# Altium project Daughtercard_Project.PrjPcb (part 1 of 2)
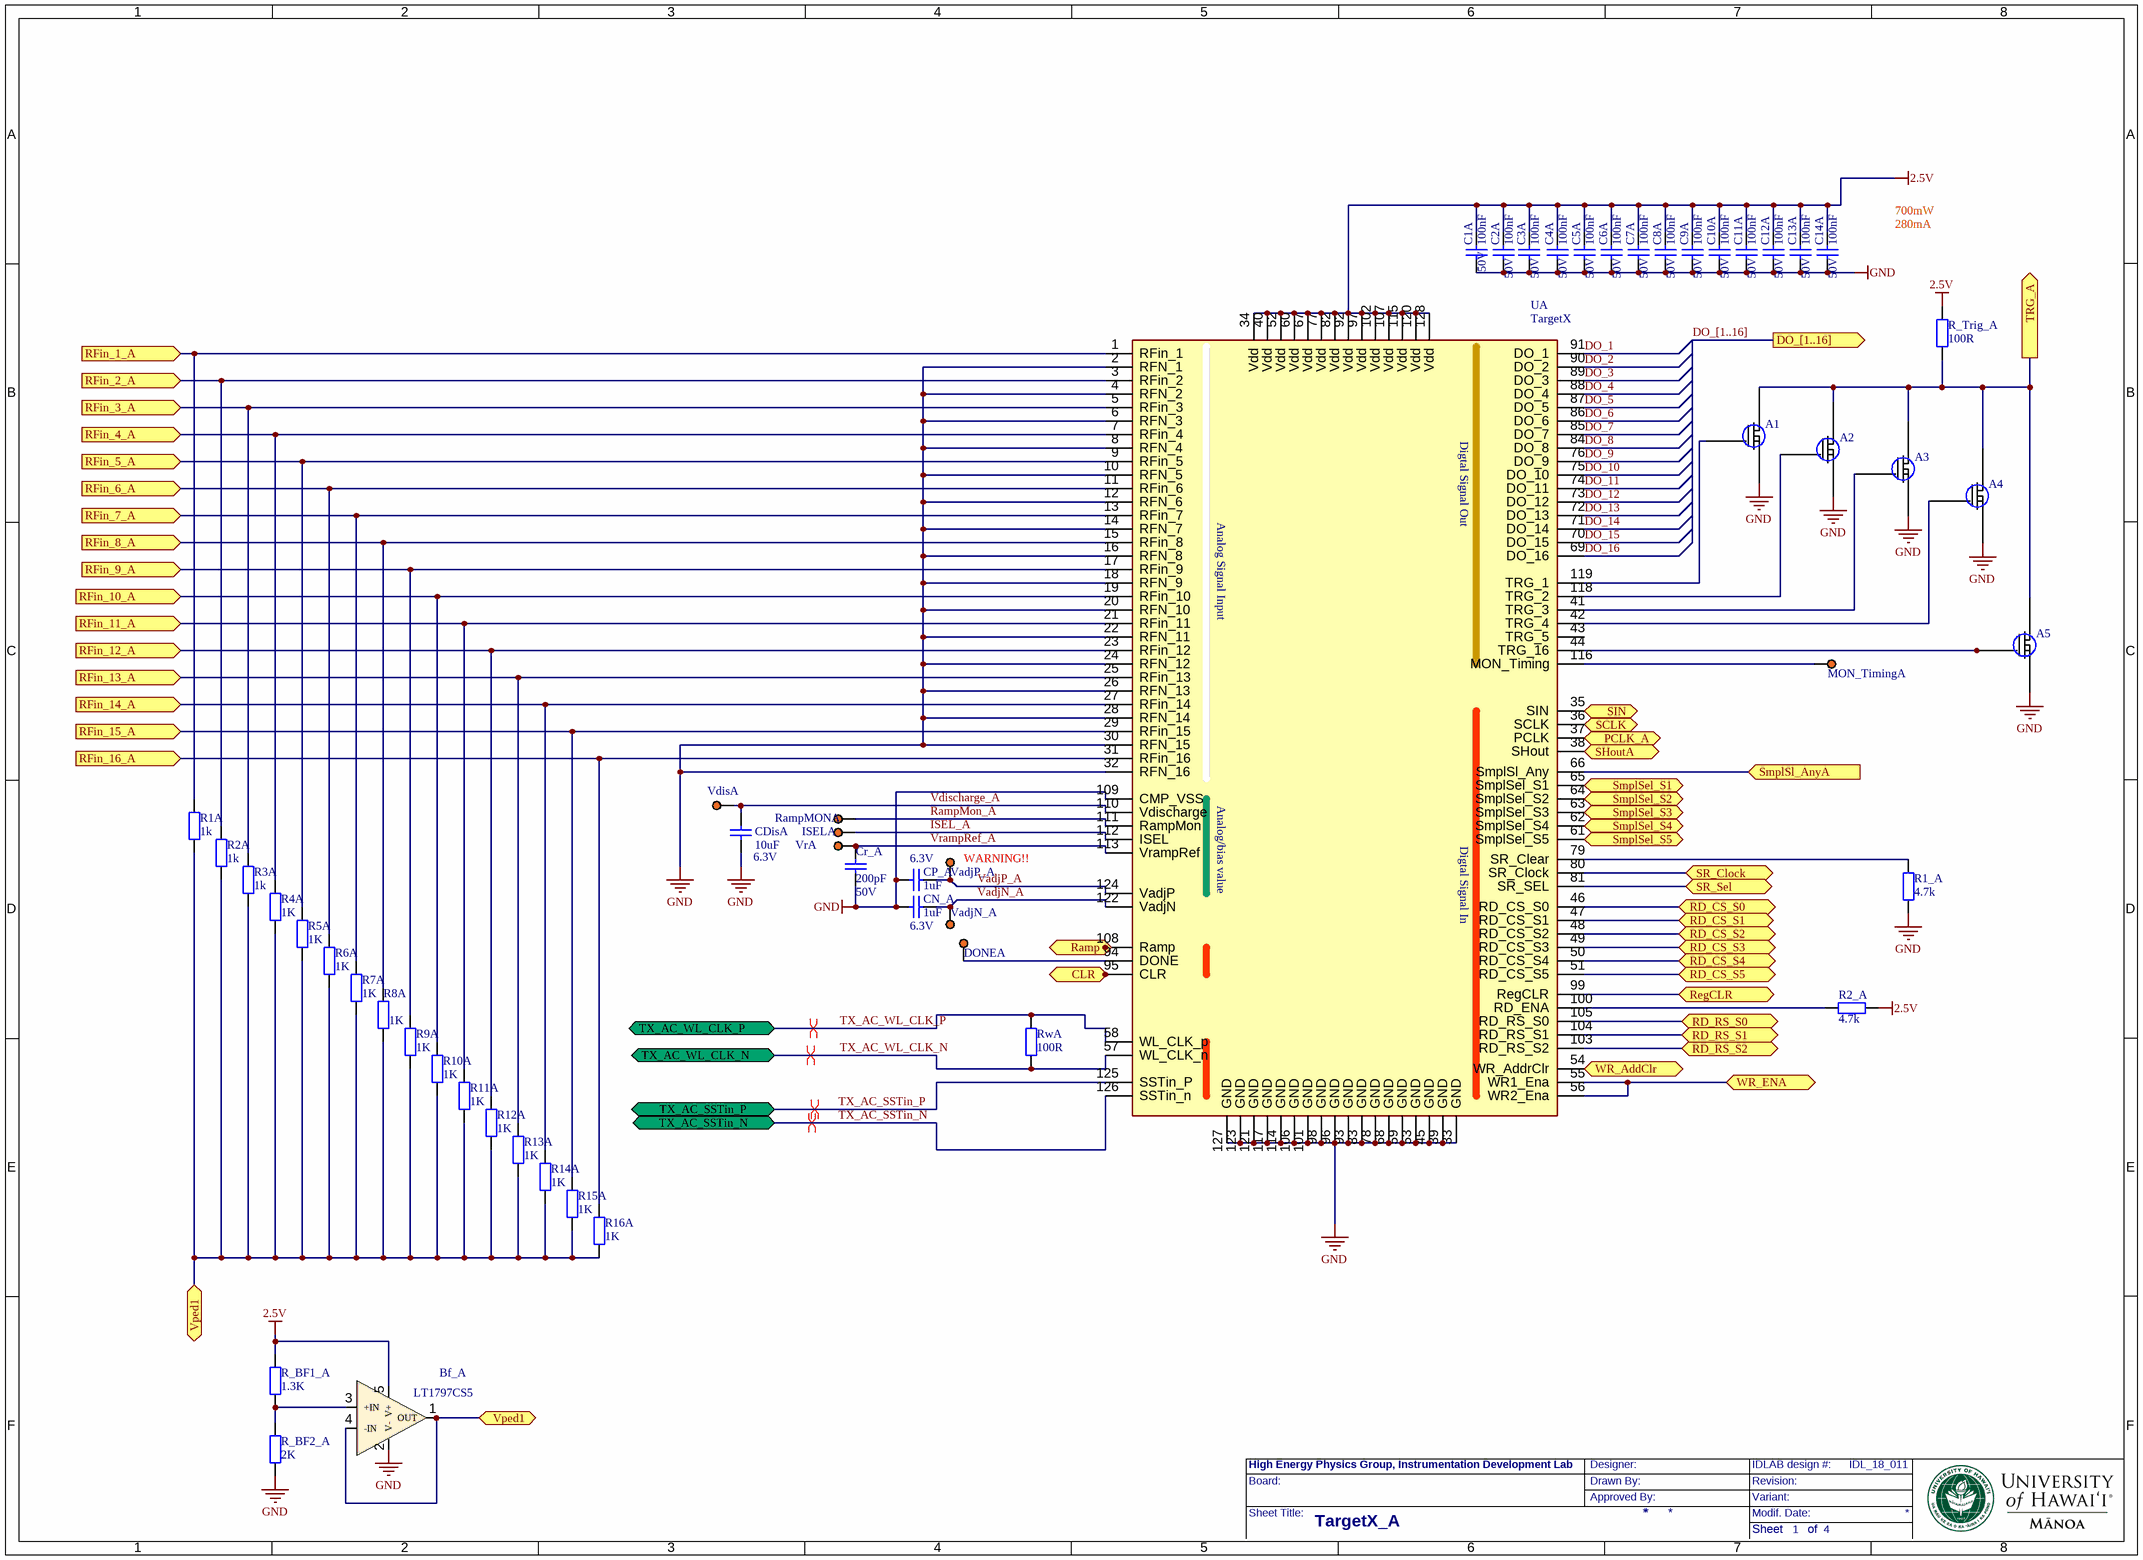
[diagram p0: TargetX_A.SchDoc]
5 sheets, 222 parts. Net scope: flat (ports and power ports of the same name join across sheets).
Board file: Daughter_Card_Tommy3.PcbDoc
Sheets:
  TargetX_A.SchDoc
  TargetX_B.SchDoc
  TargetX_C.SchDoc
  TargetX_D.SchDoc
  Daughtercard_Input_Output.SchDoc

## Sheet TargetX_A.SchDoc
size 401 x 291 mm; DocumentNumber: 1; SheetNumber: 1; SheetTotal: 4

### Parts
A1  MOSFET  [SOT-723]  (value not drawn)
A2  MOSFET  [SOT-723]  (value not drawn)
A3  MOSFET  [SOT-723]  (value not drawn)
A4  MOSFET  [SOT-723]  (value not drawn)
A5  MOSFET  [SOT-723]  (value not drawn)
Bf_A  LT1797CS5  [TSOT23-5]
C1A  100nF  Voltage rating: 50V  [CC0402N1R]
C2A  100nF  Voltage rating: 50V  [CC0402N1R]
C3A  100nF  Voltage rating: 50V  [CC0402N1R]
C4A  100nF  Voltage rating: 50V  [CC0402N1R]
C5A  100nF  Voltage rating: 50V  [CC0402N1R]
C6A  100nF  Voltage rating: 50V  [CC0402N1R]
C7A  100nF  Voltage rating: 50V  [CC0402N1R]
C8A  100nF  Voltage rating: 50V  [CC0402N1R]
C9A  100nF  Voltage rating: 50V  [CC0402N1R]
C10A  100nF  Voltage rating: 50V  [CC0402N1R]
C11A  100nF  Voltage rating: 50V  [CC0402N1R]
C12A  100nF  Voltage rating: 50V  [CC0402N1R]
C13A  100nF  Voltage rating: 50V  [CC0402N1R]
C14A  100nF  Voltage rating: 50V  [CC0402N1R]
CDisA  10uF  Voltage rating: 6.3V  [CC0402N1R]
CN_A  1uF  Voltage rating: 6.3V  [CC0402N1R]
CP_A  1uF  Voltage rating: 6.3V  [CC0402N1R]
Cr_A  200pF  Voltage rating: 50V  [CC0402N1R]
DONEA  SP1.5S  [SP1.5SQ]  (value not drawn)  (no BOM)
ISELA  SP1.5S  [SP1.5SQ]  (value not drawn)  (no BOM)
MON_TimingA  SP1.5S  [SP1.5SQ]  (value not drawn)  (no BOM)
R1_A  4.7k  [RC0603N1R]
R1A  1k  [RC0402N1R]
R2_A  4.7k  [RC0603N1R]
R2A  1k  [RC0402N1R]
R3A  1k  [RC0402N1R]
R4A  1K  [RC0402N1R]
R5A  1K  [RC0402N1R]
R6A  1K  [RC0402N1R]
R7A  1K  [RC0402N1R]
R8A  1K  [RC0402N1R]
R9A  1K  [RC0402N1R]
R10A  1K  [RC0402N1R]
R11A  1K  [RC0402N1R]
R12A  1K  [RC0402N1R]
R13A  1K  [RC0402N1R]
R14A  1K  [RC0402N1R]
R15A  1K  [RC0402N1R]
R16A  1K  [RC0402N1R]
R_BF1_A  1.3K  [RC0402N1R]
R_BF2_A  2K  [RC0402N1R]
R_Trig_A  100R  [RC0805N1R]
RampMONA  SP1.5S  [SP1.5SQ]  (value not drawn)  (no BOM)
RwA  100R  [RC0402N1R]
UA  TargetX  [TQFP128_MZA]
VadjN_A  SP1.5S  [SP1.5SQ]  (value not drawn)  (no BOM)
VadjP_A  SP1.5S  [SP1.5SQ]  (value not drawn)  (no BOM)
VdisA  SP1.5S  [SP1.5SQ]  (value not drawn)  (no BOM)
VrA  SP1.5S  [SP1.5SQ]  (value not drawn)  (no BOM)

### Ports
CLR (bidir), DO_[1..16] (out), PCLK_A (bidir), Ramp (bidir), RD_CS_S0 (bidir), RD_CS_S1 (bidir), RD_CS_S2 (bidir), RD_CS_S3 (bidir), RD_CS_S4 (bidir), RD_CS_S5 (bidir), RD_RS_S0 (bidir), RD_RS_S1 (bidir), RD_RS_S2 (bidir), RegCLR (bidir), RFin_1_A (in), RFin_2_A (in), RFin_3_A (in), RFin_4_A (in), RFin_5_A (in), RFin_6_A (in), RFin_7_A (in), RFin_8_A (in), RFin_9_A (in), RFin_10_A (in), RFin_11_A (in), RFin_12_A (in), RFin_13_A (in), RFin_14_A (in), RFin_15_A (in), RFin_16_A (in), SCLK (bidir), SHoutA (bidir), SIN (bidir), SmplSel_S1 (bidir), SmplSel_S2 (bidir), SmplSel_S3 (bidir), SmplSel_S4 (bidir), SmplSel_S5 (bidir), SmplSl_AnyA (in), SR_Clock (bidir), SR_Sel (bidir), TRG_A (out), TX_AC_SSTin_N (bidir), TX_AC_SSTin_P (bidir), TX_AC_WL_CLK_N (bidir), TX_AC_WL_CLK_P (bidir), Vped1 (bidir), WR_AddClr (bidir), WR_ENA (bidir)

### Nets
2.5V: Bf_A.5(V+) C1A.2 C2A.2 C3A.2 C4A.2 C5A.2 C6A.2 C7A.2 C8A.2 C9A.2 C10A.2 C11A.2 C12A.2 C13A.2 C14A.2 R2_A.1 R_BF1_A.2 R_Trig_A.2 UA.34(Vdd) UA.40(Vdd) UA.52(Vdd) UA.60(Vdd) UA.67(Vdd) UA.77(Vdd) UA.82(Vdd) UA.92(Vdd) UA.97(Vdd) UA.102(Vdd) UA.107(Vdd) UA.115(Vdd) UA.120(Vdd) UA.128(Vdd)
GND: A1.2(Source) A2.2(Source) A3.2(Source) A4.2(Source) A5.2(Source) Bf_A.2(V-) C1A.1 C2A.1 C3A.1 C4A.1 C5A.1 C6A.1 C7A.1 C8A.1 C9A.1 C10A.1 C11A.1 C12A.1 C13A.1 C14A.1 CDisA.1 CN_A.1 CP_A.1 Cr_A.1 R1_A.1 R_BF2_A.1 UA.2(RFN_1) UA.4(RFN_2) UA.6(RFN_3) UA.8(RFN_4) UA.10(RFN_5) UA.12(RFN_6) UA.14(RFN_7) UA.16(RFN_8) UA.18(RFN_9) UA.20(RFN_10) UA.22(RFN_11) UA.24(RFN_12) UA.26(RFN_13) UA.28(RFN_14) UA.30(RFN_15) UA.32(RFN_16) UA.33(GND) UA.39(GND) UA.45(GND) UA.53(GND) UA.59(GND) UA.68(GND) UA.78(GND) UA.83(GND) UA.93(GND) UA.96(GND) UA.98(GND) UA.101(GND) UA.106(GND) UA.109(CMP_VSS) UA.114(GND) UA.117(GND) UA.121(GND) UA.123(GND) UA.127(GND)
DO_1: UA.91(DO_1)
DO_2: UA.90(DO_2)
DO_3: UA.89(DO_3)
DO_4: UA.88(DO_4)
DO_5: UA.87(DO_5)
DO_6: UA.86(DO_6)
DO_7: UA.85(DO_7)
DO_8: UA.84(DO_8)
DO_9: UA.76(DO_9)
DO_10: UA.75(DO_10)
DO_11: UA.74(DO_11)
DO_12: UA.73(DO_12)
DO_13: UA.72(DO_13)
DO_14: UA.71(DO_14)
DO_15: UA.70(DO_15)
DO_16: UA.69(DO_16)
ISEL_A: ISELA.1 UA.112(ISEL)
PCLK_A: UA.37(PCLK) ; port PCLK_A
RampMon_A: RampMONA.1 UA.111(RampMon)
RD_CS_S0: UA.46(RD_CS_S0) ; port RD_CS_S0
RD_CS_S1: UA.47(RD_CS_S1) ; port RD_CS_S1
RD_CS_S2: UA.48(RD_CS_S2) ; port RD_CS_S2
RD_CS_S3: UA.49(RD_CS_S3) ; port RD_CS_S3
RD_CS_S4: UA.50(RD_CS_S4) ; port RD_CS_S4
RD_CS_S5: UA.51(RD_CS_S5) ; port RD_CS_S5
RD_RS_S0: UA.105(RD_RS_S0) ; port RD_RS_S0
RD_RS_S1: UA.104(RD_RS_S1) ; port RD_RS_S1
RD_RS_S2: UA.103(RD_RS_S2) ; port RD_RS_S2
RegCLR: UA.99(RegCLR) ; port RegCLR
RFin_1_A: R1A.2 UA.1(RFin_1) ; port RFin_1_A
RFin_2_A: R2A.2 UA.3(RFin_2) ; port RFin_2_A
RFin_3_A: R3A.2 UA.5(RFin_3) ; port RFin_3_A
RFin_4_A: R4A.2 UA.7(RFin_4) ; port RFin_4_A
RFin_5_A: R5A.2 UA.9(RFin_5) ; port RFin_5_A
RFin_6_A: R6A.2 UA.11(RFin_6) ; port RFin_6_A
RFin_7_A: R7A.2 UA.13(RFin_7) ; port RFin_7_A
RFin_8_A: R8A.2 UA.15(RFin_8) ; port RFin_8_A
RFin_9_A: R9A.2 UA.17(RFin_9) ; port RFin_9_A
RFin_10_A: R10A.2 UA.19(RFin_10) ; port RFin_10_A
RFin_11_A: R11A.2 UA.21(RFin_11) ; port RFin_11_A
RFin_12_A: R12A.2 UA.23(RFin_12) ; port RFin_12_A
RFin_13_A: R13A.2 UA.25(RFin_13) ; port RFin_13_A
RFin_14_A: R14A.2 UA.27(RFin_14) ; port RFin_14_A
RFin_15_A: R15A.2 UA.29(RFin_15) ; port RFin_15_A
RFin_16_A: R16A.2 UA.31(RFin_16) ; port RFin_16_A
SCLK: UA.36(SCLK) ; port SCLK
SHoutA: UA.38(SHout) ; port SHoutA
SIN: UA.35(SIN) ; port SIN
SmplSel_S1: UA.65(SmplSel_S1) ; port SmplSel_S1
SmplSel_S2: UA.64(SmplSel_S2) ; port SmplSel_S2
SmplSel_S3: UA.63(SmplSel_S3) ; port SmplSel_S3
SmplSel_S4: UA.62(SmplSel_S4) ; port SmplSel_S4
SmplSel_S5: UA.61(SmplSel_S5) ; port SmplSel_S5
SmplSl_AnyA: UA.66(SmplSl_Any) ; port SmplSl_AnyA
SR_Clock: UA.80(SR_Clock) ; port SR_Clock
SR_Sel: UA.81(SR_SEL) ; port SR_Sel
TRG_A: A1.3(Drain) A2.3(Drain) A3.3(Drain) A4.3(Drain) A5.3(Drain) R_Trig_A.1 ; port TRG_A
TX_AC_SSTin_N: UA.126(SSTin_n) ; port TX_AC_SSTin_N
TX_AC_SSTin_P: UA.125(SSTin_P) ; port TX_AC_SSTin_P
TX_AC_WL_CLK_N: RwA.1 UA.57(WL_CLK_n) ; port TX_AC_WL_CLK_N
TX_AC_WL_CLK_P: RwA.2 UA.58(WL_CLK_p) ; port TX_AC_WL_CLK_P
VadjN_A: CN_A.2 UA.122(VadjN) VadjN_A.1
VadjP_A: CP_A.2 UA.124(VadjP) VadjP_A.1
Vdischarge_A: CDisA.2 UA.110(Vdischarge) VdisA.1
Vped1: Bf_A.1(OUT) Bf_A.4(-IN) R1A.1 R2A.1 R3A.1 R4A.1 R5A.1 R6A.1 R7A.1 R8A.1 R9A.1 R10A.1 R11A.1 R12A.1 R13A.1 R14A.1 R15A.1 R16A.1 ; port Vped1
VrampRef_A: Cr_A.2 UA.113(VrampRef) VrA.1
WR_AddClr: UA.54(WR_AddrClr) ; port WR_AddClr
WR_ENA: UA.55(WR1_Ena) UA.56(WR2_Ena) ; port WR_ENA
NetA1_1: A1.1(Gate) UA.119(TRG_1)
NetA2_1: A2.1(Gate) UA.118(TRG_2)
NetA3_1: A3.1(Gate) UA.41(TRG_3)
NetA4_1: A4.1(Gate) UA.42(TRG_4)
NetA5_1: A5.1(Gate) UA.44(TRG_16)
NetBf_A_3: Bf_A.3(+IN) R_BF1_A.1 R_BF2_A.2
NetDONEA_1: DONEA.1 UA.94(DONE)
NetMON_TimingA_1: MON_TimingA.1 UA.116(MON_Timing)
NetR1_A_2: R1_A.2 UA.79(SR_Clear)
NetR2_A_2: R2_A.2 UA.100(RD_ENA)

Not connected (* = marked no-connect by the designer): UA 43(TRG_5) 95(CLR) 108(Ramp)

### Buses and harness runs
bus DO_[1..16] = port DO_[1..16]

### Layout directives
differential pair; rule Differential Pairs Routing [Pref Gap = 10mil    Min Gap  = 10mil    Max Gap  = 10milPref Width = 15mil    Min Width  = 15mil    Max Width  = 15mil]: TX_AC_SSTin_N, TX_AC_SSTin_P, TX_AC_WL_CLK_N, TX_AC_WL_CLK_P

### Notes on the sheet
- 700mW
- 280mA
- (near VadjP_A) WARNING!!
- Board:
- High Energy Physics Group, Instrumentation Development Lab
- Drawn By:
- Designer:
- Approved By:
- Revision:
- IDLAB design #:
- Variant:
- IDL_18_011
- Sheet Title:
- TargetX_A
- Modif. Date:
- Sheet       of

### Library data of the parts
A1-A5 = RUM001L02: N-Channel 20V 100mA (Ta) 150mW (Ta) Surface Mount VMT3
Bf_A = LT1797CS5#TRMPBF: Buffer Op-Amp
C1A C2A C3A C4A C5A C6A C7A C8A C9A C10A C11A C12A C13A C14A = CAPCC0402_100N_50VX7R: 0.10µF 50V Ceramic Capacitor X7R 0402; Manufacturer: TDK; Manufacturer No: C1005X7R1H104K050BB; Tech: SMDR
CDisA CN_A CP_A = CAPCC0402_1.0U_50VX7R: 1µF 6.3V Ceramic Capacitor X7R 0402; Manufacturer: TDK; Manufacturer No: GRM155R70J105KA12D; Tech: SMDR
Cr_A = CAPCC0402_200P_50VNP0: Capacitor chip ceramic 0402 50V NPO; Manufacturer: Murata; Manufacturer No: GRM1555C1H201JA01D; Tech: SMDR
DONEA ISELA MON_TimingA RampMONA VadjN_A VadjP_A VdisA VrA = SP1.5S: Wire solder pin 1.5mm; Sort: 610; Tech: THDW
R1_A R2_A = RES0603-1-1.00K-1%100PPM: Chip Resistor 0603 100mW 1% 100ppm; Manufacturer: Yageo; Manufacturer No: RC0603FR-071KL; Tech: SMDR
R1A R2A R3A R4A R5A R6A R7A R8A R9A R10A R11A R12A R13A R14A R15A R16A R_BF1_A R_BF2_A = RES0402-0-0R-1%100PPM: Chip Resistor 0402 62.5mW 1% 100ppm; Manufacturer: Panasonic; Manufacturer No: ERJ-2GE0R00X; Tech: SMDR
R_Trig_A = RES0805: Chip Resistor 0805; Tech: SMDR; Comment2: 0.125W 1% 200ppm; Sort: 110
RwA = RES0402-100R-1%100PPM: RES SMD 100 OHM 1% 1/10W 0402; Manufacturer: Panasonic; Manufacturer No: ERJ-2RKF1000X; Tech: SMDR
UA = DIGITZ_TargetX: 16-channel, 1GSPS Transient Waveform Recorder; Manufacturer: UHM_IDL; Tech: SMDR

## Sheet TargetX_B.SchDoc
size 401 x 291 mm; DocumentNumber: 2; SheetNumber: 2; SheetTotal: 4
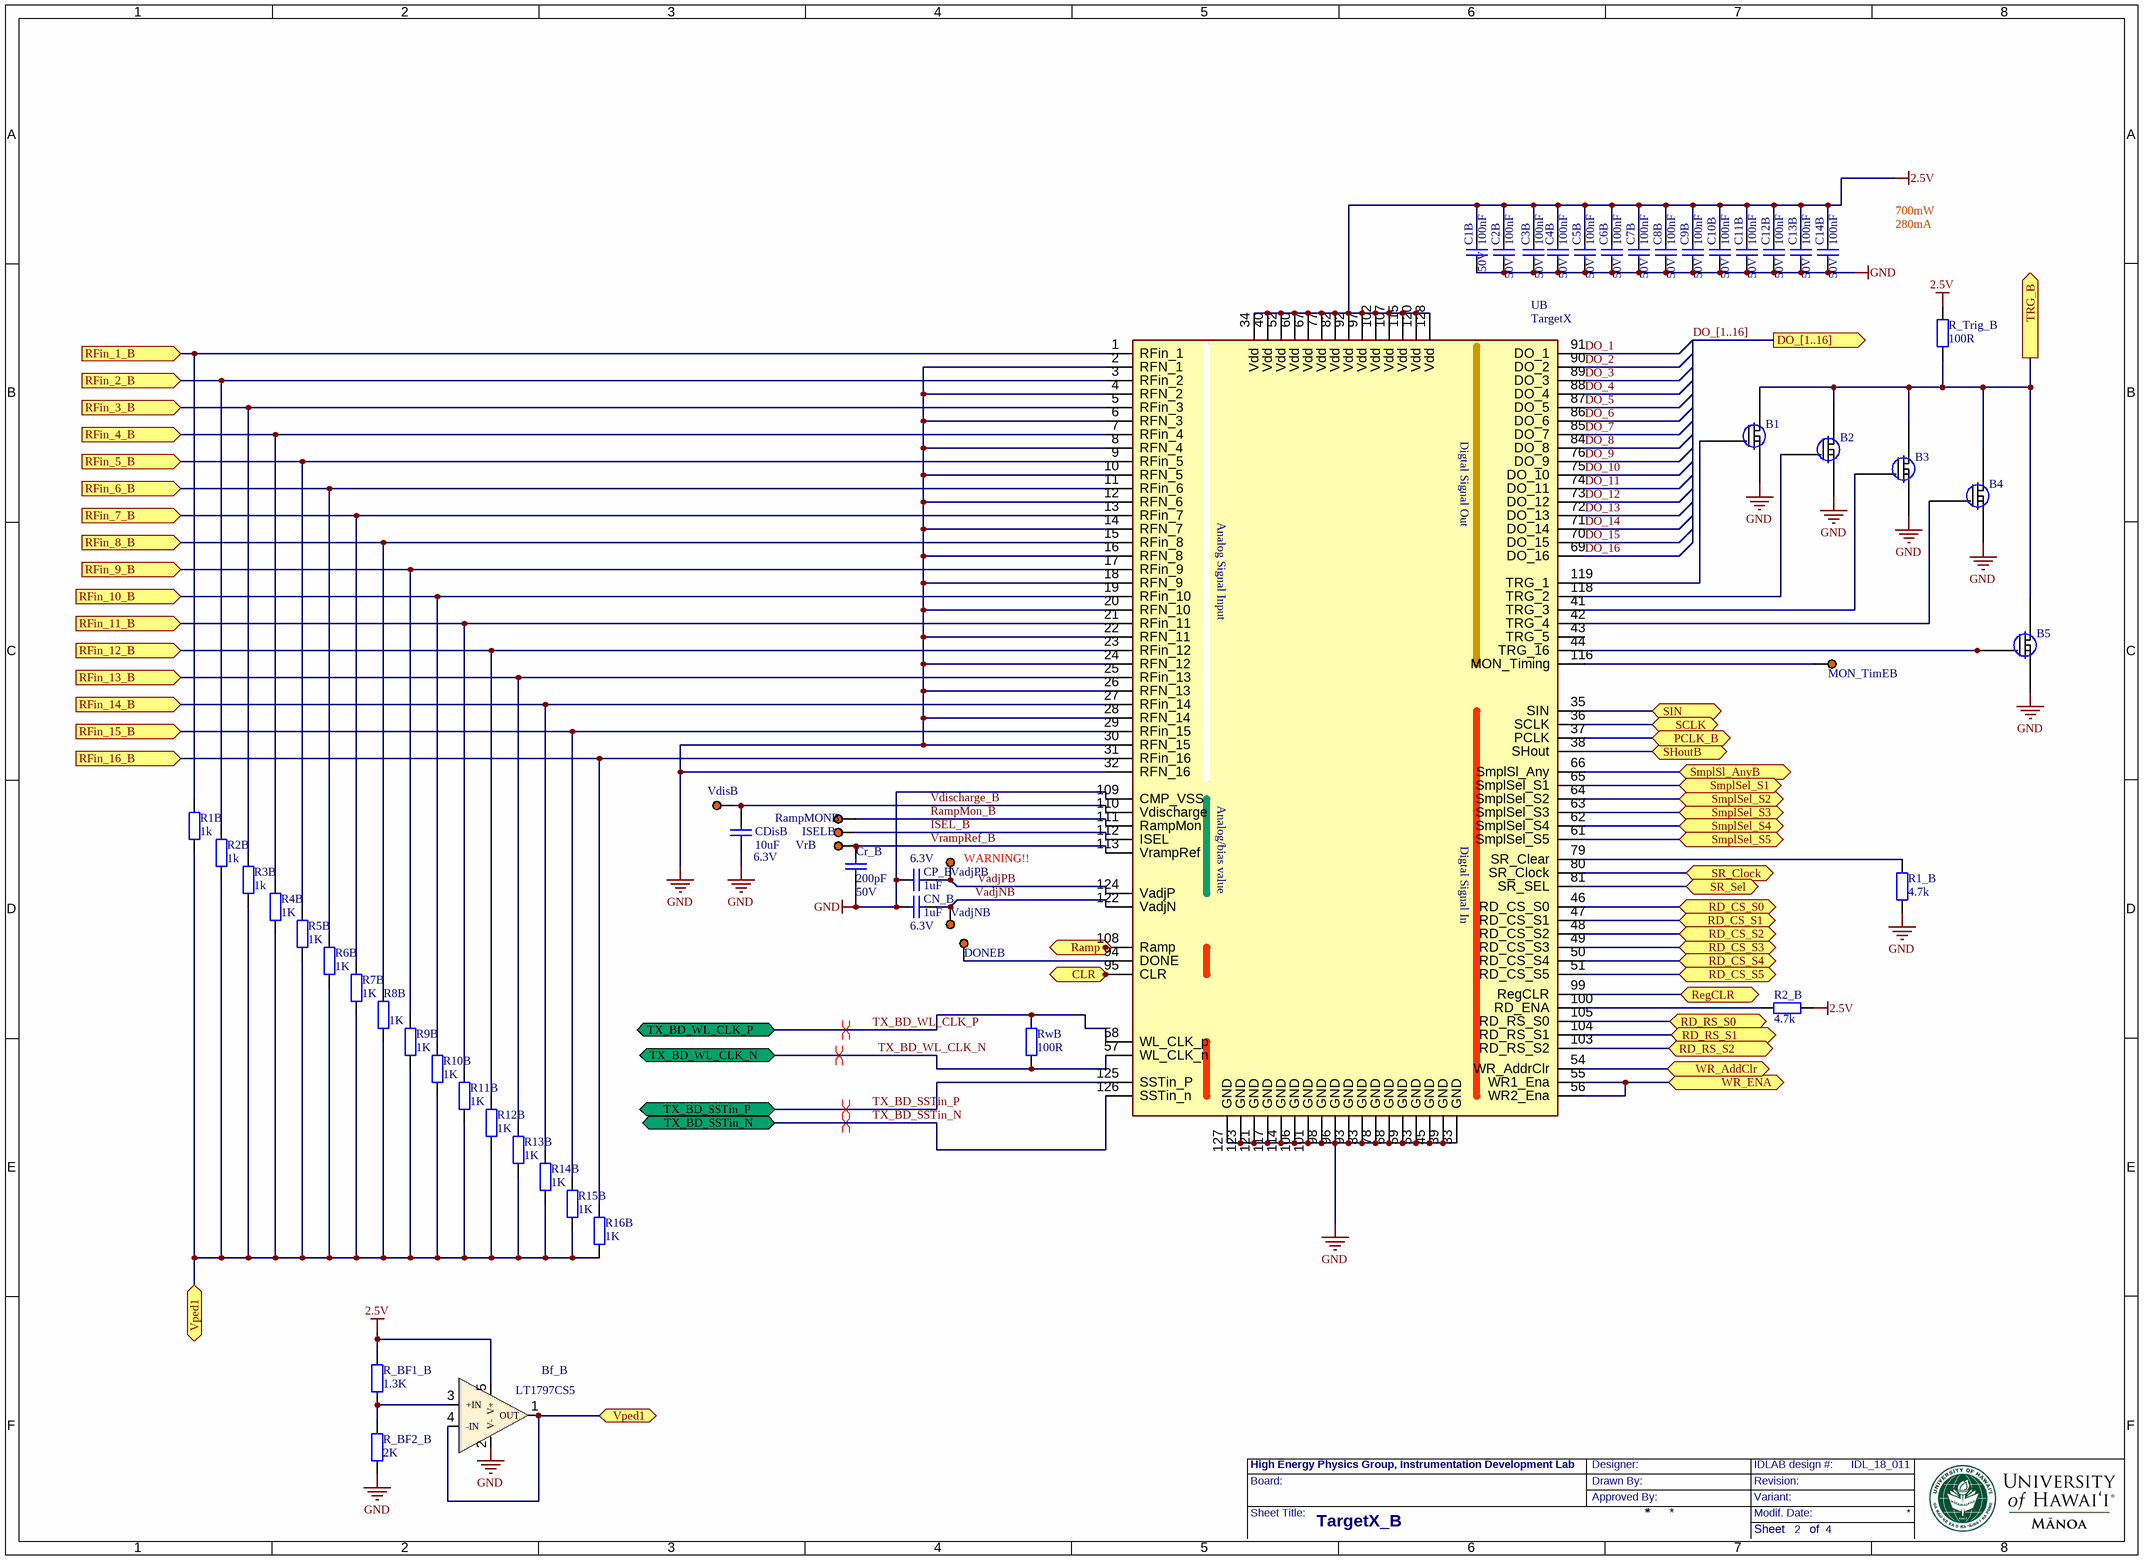
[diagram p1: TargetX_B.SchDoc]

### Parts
B1  MOSFET  [SOT-723]  (value not drawn)
B2  MOSFET  [SOT-723]  (value not drawn)
B3  MOSFET  [SOT-723]  (value not drawn)
B4  MOSFET  [SOT-723]  (value not drawn)
B5  MOSFET  [SOT-723]  (value not drawn)
Bf_B  LT1797CS5  [TSOT23-5]
C1B  100nF  Voltage rating: 50V  [CC0402N1R]
C2B  100nF  Voltage rating: 50V  [CC0402N1R]
C3B  100nF  Voltage rating: 50V  [CC0402N1R]
C4B  100nF  Voltage rating: 50V  [CC0402N1R]
C5B  100nF  Voltage rating: 50V  [CC0402N1R]
C6B  100nF  Voltage rating: 50V  [CC0402N1R]
C7B  100nF  Voltage rating: 50V  [CC0402N1R]
C8B  100nF  Voltage rating: 50V  [CC0402N1R]
C9B  100nF  Voltage rating: 50V  [CC0402N1R]
C10B  100nF  Voltage rating: 50V  [CC0402N1R]
C11B  100nF  Voltage rating: 50V  [CC0402N1R]
C12B  100nF  Voltage rating: 50V  [CC0402N1R]
C13B  100nF  Voltage rating: 50V  [CC0402N1R]
C14B  100nF  Voltage rating: 50V  [CC0402N1R]
CDisB  10uF  Voltage rating: 6.3V  [CC0402N1R]
CN_B  1uF  Voltage rating: 6.3V  [CC0402N1R]
CP_B  1uF  Voltage rating: 6.3V  [CC0402N1R]
Cr_B  200pF  Voltage rating: 50V  [CC0402N1R]
DONEB  SP1.5S  [SP1.5SQ]  (value not drawn)  (no BOM)
ISELB  SP1.5S  [SP1.5SQ]  (value not drawn)  (no BOM)
MON_TimEB  SP1.5S  [SP1.5SQ]  (value not drawn)  (no BOM)
R1_B  4.7k  [RC0603N1R]
R1B  1k  [RC0402N1R]
R2_B  4.7k  [RC0603N1R]
R2B  1k  [RC0402N1R]
R3B  1k  [RC0402N1R]
R4B  1K  [RC0402N1R]
R5B  1K  [RC0402N1R]
R6B  1K  [RC0402N1R]
R7B  1K  [RC0402N1R]
R8B  1K  [RC0402N1R]
R9B  1K  [RC0402N1R]
R10B  1K  [RC0402N1R]
R11B  1K  [RC0402N1R]
R12B  1K  [RC0402N1R]
R13B  1K  [RC0402N1R]
R14B  1K  [RC0402N1R]
R15B  1K  [RC0402N1R]
R16B  1K  [RC0402N1R]
R_BF1_B  1.3K  [RC0402N1R]
R_BF2_B  2K  [RC0402N1R]
R_Trig_B  100R  [RC0805N1R]
RampMONB  SP1.5S  [SP1.5SQ]  (value not drawn)  (no BOM)
RwB  100R  [RC0402N1R]
UB  TargetX  [TQFP128_MZA]
VadjNB  SP1.5S  [SP1.5SQ]  (value not drawn)  (no BOM)
VadjPB  SP1.5S  [SP1.5SQ]  (value not drawn)  (no BOM)
VdisB  SP1.5S  [SP1.5SQ]  (value not drawn)  (no BOM)
VrB  SP1.5S  [SP1.5SQ]  (value not drawn)  (no BOM)

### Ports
CLR (bidir), DO_[1..16] (out), PCLK_B (bidir), Ramp (bidir), RD_CS_S0 (bidir), RD_CS_S1 (bidir), RD_CS_S2 (bidir), RD_CS_S3 (bidir), RD_CS_S4 (bidir), RD_CS_S5 (bidir), RD_RS_S0 (bidir), RD_RS_S1 (bidir), RD_RS_S2 (bidir), RegCLR (bidir), RFin_1_B (in), RFin_2_B (in), RFin_3_B (in), RFin_4_B (in), RFin_5_B (in), RFin_6_B (in), RFin_7_B (in), RFin_8_B (in), RFin_9_B (in), RFin_10_B (in), RFin_11_B (in), RFin_12_B (in), RFin_13_B (in), RFin_14_B (in), RFin_15_B (in), RFin_16_B (in), SCLK (bidir), SHoutB (bidir), SIN (bidir), SmplSel_S1 (bidir), SmplSel_S2 (bidir), SmplSel_S3 (bidir), SmplSel_S4 (bidir), SmplSel_S5 (bidir), SmplSl_AnyB (bidir), SR_Clock (bidir), SR_Sel (bidir), TRG_B (out), TX_BD_SSTin_N (bidir), TX_BD_SSTin_P (bidir), TX_BD_WL_CLK_N (bidir), TX_BD_WL_CLK_P (bidir), Vped1 (bidir), WR_AddClr (bidir), WR_ENA (bidir)

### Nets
2.5V: Bf_B.5(V+) C1B.2 C2B.2 C3B.2 C4B.2 C5B.2 C6B.2 C7B.2 C8B.2 C9B.2 C10B.2 C11B.2 C12B.2 C13B.2 C14B.2 R2_B.1 R_BF1_B.2 R_Trig_B.2 UB.34(Vdd) UB.40(Vdd) UB.52(Vdd) UB.60(Vdd) UB.67(Vdd) UB.77(Vdd) UB.82(Vdd) UB.92(Vdd) UB.97(Vdd) UB.102(Vdd) UB.107(Vdd) UB.115(Vdd) UB.120(Vdd) UB.128(Vdd)
GND: B1.2 B2.2 B3.2 B4.2 B5.2 Bf_B.2(V-) C1B.1 C2B.1 C3B.1 C4B.1 C5B.1 C6B.1 C7B.1 C8B.1 C9B.1 C10B.1 C11B.1 C12B.1 C13B.1 C14B.1 CDisB.1 CN_B.1 CP_B.1 Cr_B.1 R1_B.1 R_BF2_B.1 UB.2(RFN_1) UB.4(RFN_2) UB.6(RFN_3) UB.8(RFN_4) UB.10(RFN_5) UB.12(RFN_6) UB.14(RFN_7) UB.16(RFN_8) UB.18(RFN_9) UB.20(RFN_10) UB.22(RFN_11) UB.24(RFN_12) UB.26(RFN_13) UB.28(RFN_14) UB.30(RFN_15) UB.32(RFN_16) UB.33(GND) UB.39(GND) UB.45(GND) UB.53(GND) UB.59(GND) UB.68(GND) UB.78(GND) UB.83(GND) UB.93(GND) UB.96(GND) UB.98(GND) UB.101(GND) UB.106(GND) UB.109(CMP_VSS) UB.114(GND) UB.117(GND) UB.121(GND) UB.123(GND) UB.127(GND)
DO_1: UB.91(DO_1)
DO_2: UB.90(DO_2)
DO_3: UB.89(DO_3)
DO_4: UB.88(DO_4)
DO_5: UB.87(DO_5)
DO_6: UB.86(DO_6)
DO_7: UB.85(DO_7)
DO_8: UB.84(DO_8)
DO_9: UB.76(DO_9)
DO_10: UB.75(DO_10)
DO_11: UB.74(DO_11)
DO_12: UB.73(DO_12)
DO_13: UB.72(DO_13)
DO_14: UB.71(DO_14)
DO_15: UB.70(DO_15)
DO_16: UB.69(DO_16)
ISEL_B: ISELB.1 UB.112(ISEL)
PCLK_B: UB.37(PCLK) ; port PCLK_B
RampMon_B: RampMONB.1 UB.111(RampMon)
RD_CS_S0: UB.46(RD_CS_S0) ; port RD_CS_S0
RD_CS_S1: UB.47(RD_CS_S1) ; port RD_CS_S1
RD_CS_S2: UB.48(RD_CS_S2) ; port RD_CS_S2
RD_CS_S3: UB.49(RD_CS_S3) ; port RD_CS_S3
RD_CS_S4: UB.50(RD_CS_S4) ; port RD_CS_S4
RD_CS_S5: UB.51(RD_CS_S5) ; port RD_CS_S5
RD_RS_S0: UB.105(RD_RS_S0) ; port RD_RS_S0
RD_RS_S1: UB.104(RD_RS_S1) ; port RD_RS_S1
RD_RS_S2: UB.103(RD_RS_S2) ; port RD_RS_S2
RegCLR: UB.99(RegCLR) ; port RegCLR
RFin_1_B: R1B.2 UB.1(RFin_1) ; port RFin_1_B
RFin_2_B: R2B.2 UB.3(RFin_2) ; port RFin_2_B
RFin_3_B: R3B.2 UB.5(RFin_3) ; port RFin_3_B
RFin_4_B: R4B.2 UB.7(RFin_4) ; port RFin_4_B
RFin_5_B: R5B.2 UB.9(RFin_5) ; port RFin_5_B
RFin_6_B: R6B.2 UB.11(RFin_6) ; port RFin_6_B
RFin_7_B: R7B.2 UB.13(RFin_7) ; port RFin_7_B
RFin_8_B: R8B.2 UB.15(RFin_8) ; port RFin_8_B
RFin_9_B: R9B.2 UB.17(RFin_9) ; port RFin_9_B
RFin_10_B: R10B.2 UB.19(RFin_10) ; port RFin_10_B
RFin_11_B: R11B.2 UB.21(RFin_11) ; port RFin_11_B
RFin_12_B: R12B.2 UB.23(RFin_12) ; port RFin_12_B
RFin_13_B: R13B.2 UB.25(RFin_13) ; port RFin_13_B
RFin_14_B: R14B.2 UB.27(RFin_14) ; port RFin_14_B
RFin_15_B: R15B.2 UB.29(RFin_15) ; port RFin_15_B
RFin_16_B: R16B.2 UB.31(RFin_16) ; port RFin_16_B
SCLK: UB.36(SCLK) ; port SCLK
SHoutB: UB.38(SHout) ; port SHoutB
SIN: UB.35(SIN) ; port SIN
SmplSel_S1: UB.65(SmplSel_S1) ; port SmplSel_S1
SmplSel_S2: UB.64(SmplSel_S2) ; port SmplSel_S2
SmplSel_S3: UB.63(SmplSel_S3) ; port SmplSel_S3
SmplSel_S4: UB.62(SmplSel_S4) ; port SmplSel_S4
SmplSel_S5: UB.61(SmplSel_S5) ; port SmplSel_S5
SmplSl_AnyB: UB.66(SmplSl_Any) ; port SmplSl_AnyB
SR_Clock: UB.80(SR_Clock) ; port SR_Clock
SR_Sel: UB.81(SR_SEL) ; port SR_Sel
TRG_B: B1.3 B2.3 B3.3 B4.3 B5.3 R_Trig_B.1 ; port TRG_B
TX_BD_SSTin_N: UB.126(SSTin_n) ; port TX_BD_SSTin_N
TX_BD_SSTin_P: UB.125(SSTin_P) ; port TX_BD_SSTin_P
TX_BD_WL_CLK_N: RwB.1 UB.57(WL_CLK_n) ; port TX_BD_WL_CLK_N
TX_BD_WL_CLK_P: RwB.2 UB.58(WL_CLK_p) ; port TX_BD_WL_CLK_P
VadjNB: CN_B.2 UB.122(VadjN) VadjNB.1
VadjPB: CP_B.2 UB.124(VadjP) VadjPB.1
Vdischarge_B: CDisB.2 UB.110(Vdischarge) VdisB.1
Vped1: Bf_B.1(OUT) Bf_B.4(-IN) R1B.1 R2B.1 R3B.1 R4B.1 R5B.1 R6B.1 R7B.1 R8B.1 R9B.1 R10B.1 R11B.1 R12B.1 R13B.1 R14B.1 R15B.1 R16B.1 ; port Vped1
VrampRef_B: Cr_B.2 UB.113(VrampRef) VrB.1
WR_AddClr: UB.54(WR_AddrClr) ; port WR_AddClr
WR_ENA: UB.55(WR1_Ena) UB.56(WR2_Ena) ; port WR_ENA
NetB1_1: B1.1 UB.119(TRG_1)
NetB2_1: B2.1 UB.118(TRG_2)
NetB3_1: B3.1 UB.41(TRG_3)
NetB4_1: B4.1 UB.42(TRG_4)
NetB5_1: B5.1 UB.44(TRG_16)
NetBf_B_3: Bf_B.3(+IN) R_BF1_B.1 R_BF2_B.2
NetDONEB_1: DONEB.1 UB.94(DONE)
NetMON_TimEB_1: MON_TimEB.1 UB.116(MON_Timing)
NetR1_B_2: R1_B.2 UB.79(SR_Clear)
NetR2_B_2: R2_B.2 UB.100(RD_ENA)

Not connected (* = marked no-connect by the designer): UB 43(TRG_5) 95(CLR) 108(Ramp)

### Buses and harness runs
bus DO_[1..16] = port DO_[1..16]

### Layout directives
differential pair: TX_BD_SSTin_N, TX_BD_SSTin_P, TX_BD_WL_CLK_N, TX_BD_WL_CLK_P

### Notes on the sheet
- 700mW
- 280mA
- (near VadjPB) WARNING!!
- Board:
- High Energy Physics Group, Instrumentation Development Lab
- Drawn By:
- Designer:
- Approved By:
- Revision:
- IDLAB design #:
- Variant:
- IDL_18_011
- Sheet Title:
- TargetX_B
- Modif. Date:
- Sheet       of

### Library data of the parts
B1-B5 = RUM001L02: as A1 on sheet TargetX_A
Bf_B = LT1797CS5#TRMPBF: Buffer Op-Amp
C1B C2B C3B C4B C5B C6B C7B C8B C9B C10B C11B C12B C13B C14B = CAPCC0402_100N_50VX7R: as C1A on sheet TargetX_A
CDisB CN_B CP_B = CAPCC0402_1.0U_50VX7R: as CDisA on sheet TargetX_A
Cr_B = CAPCC0402_200P_50VNP0: as Cr_A on sheet TargetX_A
DONEB ISELB MON_TimEB RampMONB VadjNB VadjPB VdisB VrB = SP1.5S: as DONEA on sheet TargetX_A
R1_B R2_B = RES0603-1-1.00K-1%100PPM: as R1_A on sheet TargetX_A
R1B R2B R3B R4B R5B R6B R7B R8B R9B R10B R11B R12B R13B R14B R15B R16B R_BF1_B R_BF2_B = RES0402-0-0R-1%100PPM: as R1A on sheet TargetX_A
R_Trig_B = RES0805: as R_Trig_A on sheet TargetX_A
RwB = RES0402-100R-1%100PPM: as RwA on sheet TargetX_A
UB = DIGITZ_TargetX: as UA on sheet TargetX_A

## Sheet TargetX_C.SchDoc
size 401 x 291 mm; DocumentNumber: 3; SheetNumber: 3; SheetTotal: 4
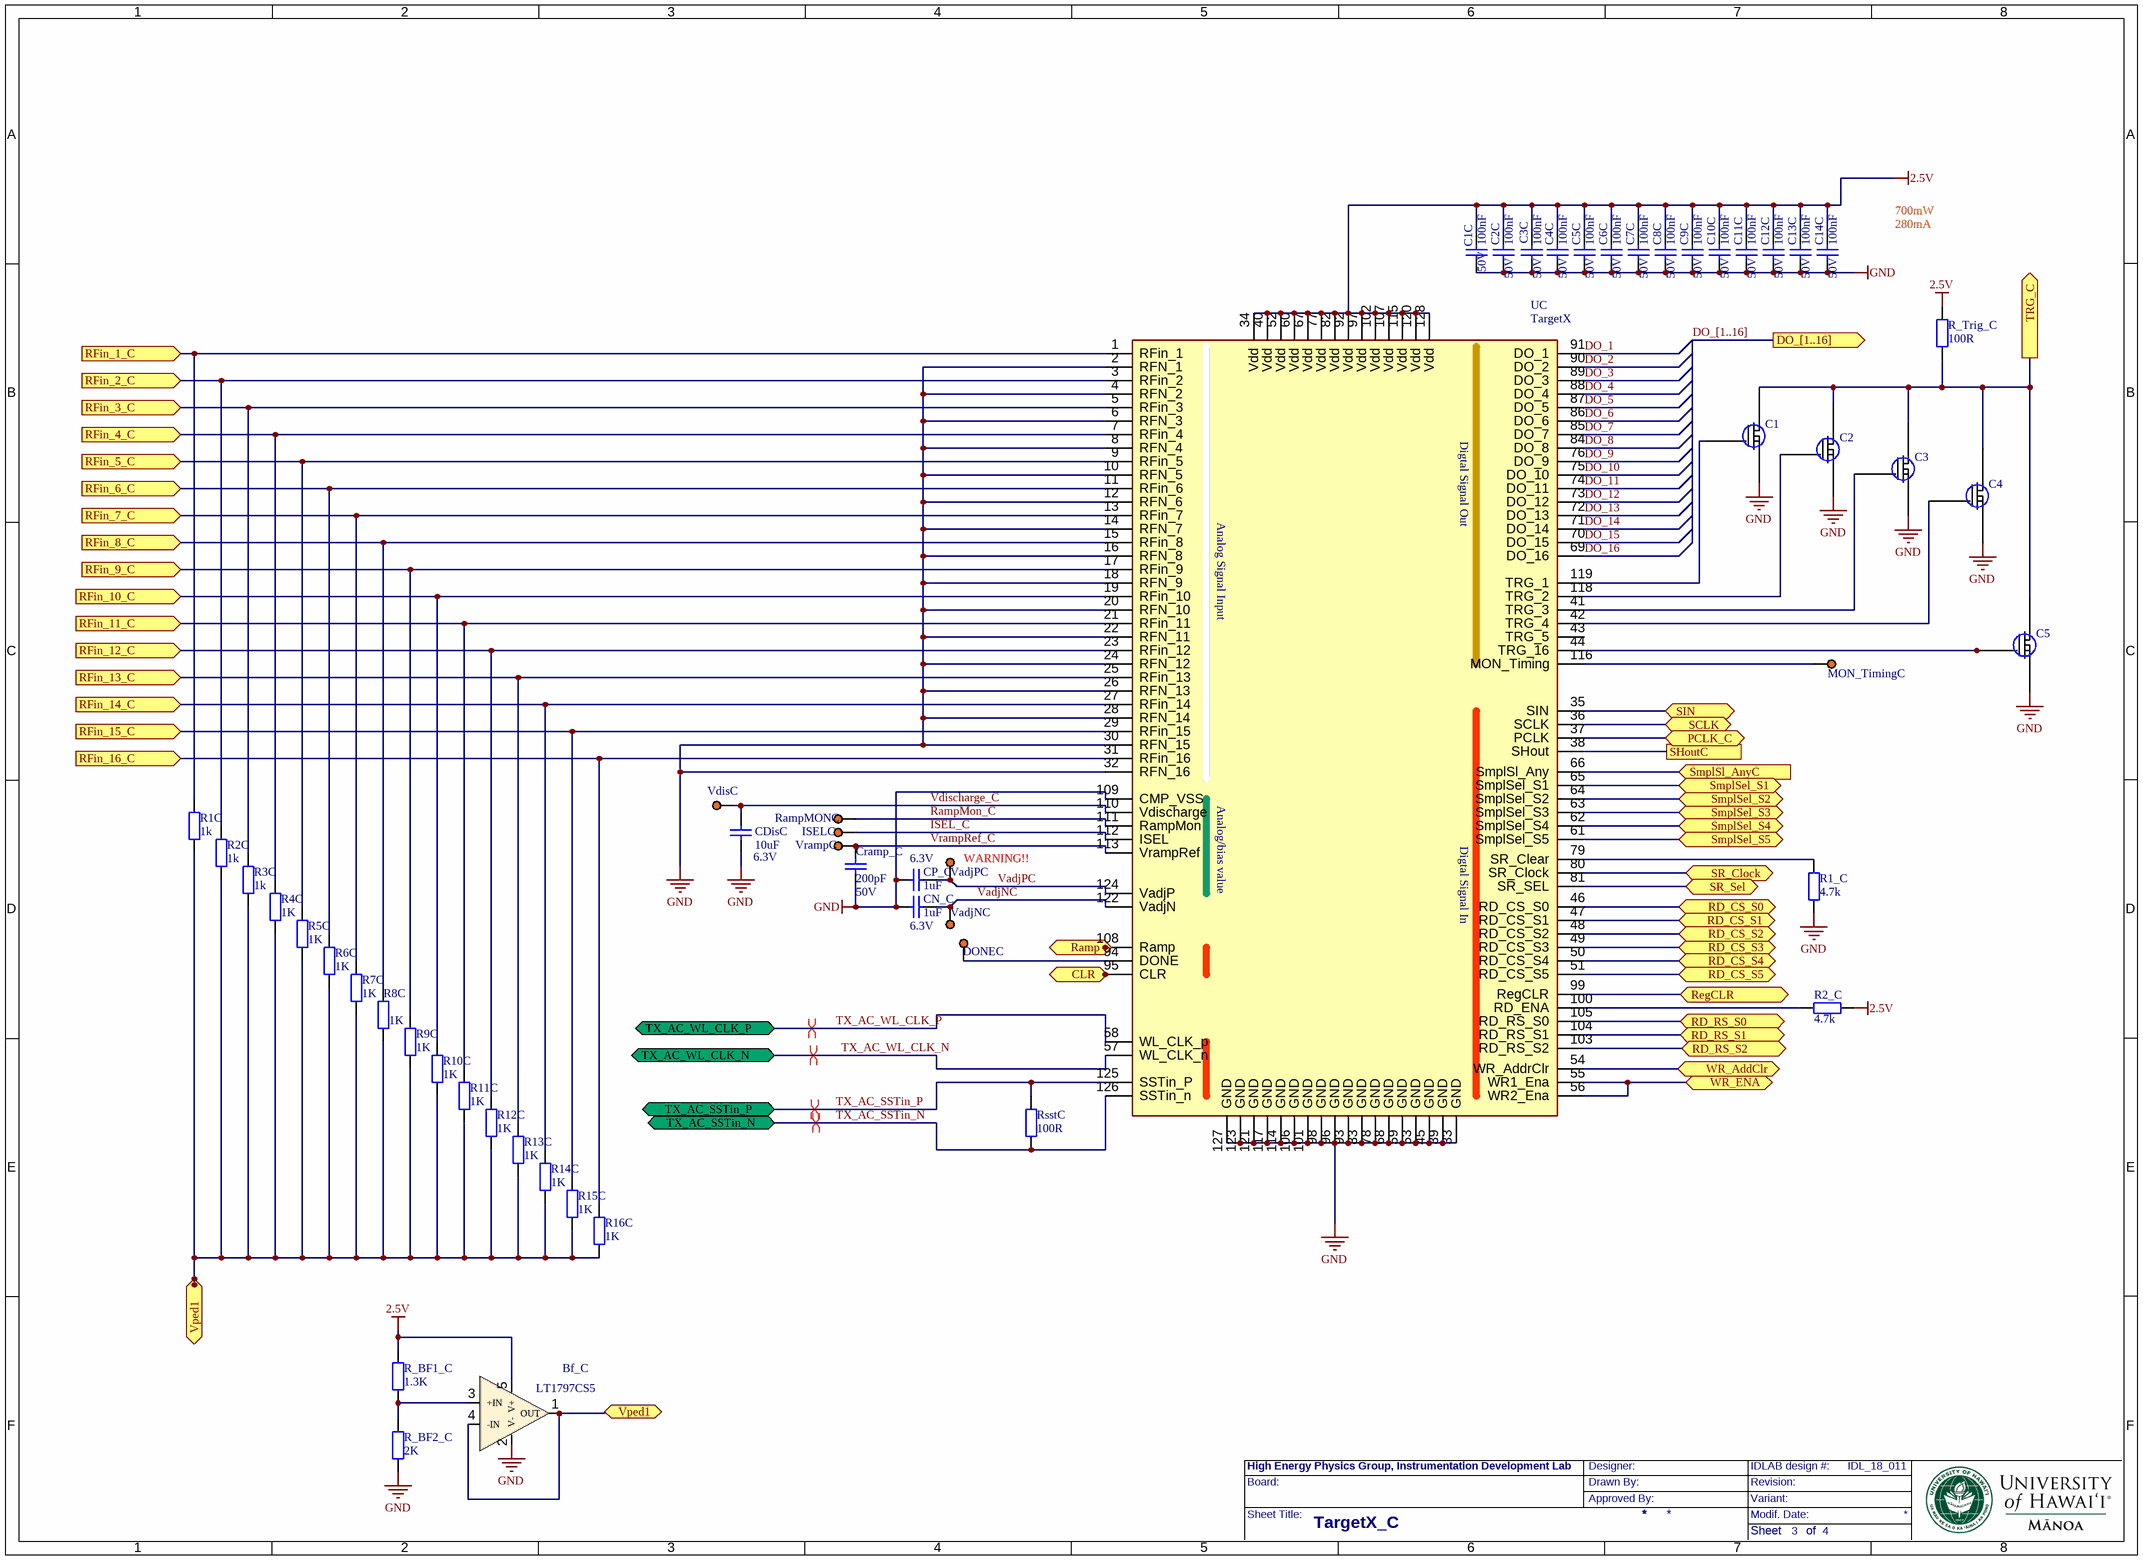
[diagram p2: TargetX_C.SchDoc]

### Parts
Bf_C  LT1797CS5  [TSOT23-5]
C1  MOSFET  [SOT-723]  (value not drawn)
C1C  100nF  Voltage rating: 50V  [CC0402N1R]
C2  MOSFET  [SOT-723]  (value not drawn)
C2C  100nF  Voltage rating: 50V  [CC0402N1R]
C3  MOSFET  [SOT-723]  (value not drawn)
C3C  100nF  Voltage rating: 50V  [CC0402N1R]
C4  MOSFET  [SOT-723]  (value not drawn)
C4C  100nF  Voltage rating: 50V  [CC0402N1R]
C5  MOSFET  [SOT-723]  (value not drawn)
C5C  100nF  Voltage rating: 50V  [CC0402N1R]
C6C  100nF  Voltage rating: 50V  [CC0402N1R]
C7C  100nF  Voltage rating: 50V  [CC0402N1R]
C8C  100nF  Voltage rating: 50V  [CC0402N1R]
C9C  100nF  Voltage rating: 50V  [CC0402N1R]
C10C  100nF  Voltage rating: 50V  [CC0402N1R]
C11C  100nF  Voltage rating: 50V  [CC0402N1R]
C12C  100nF  Voltage rating: 50V  [CC0402N1R]
C13C  100nF  Voltage rating: 50V  [CC0402N1R]
C14C  100nF  Voltage rating: 50V  [CC0402N1R]
CDisC  10uF  Voltage rating: 6.3V  [CC0402N1R]
CN_C  1uF  Voltage rating: 6.3V  [CC0402N1R]
CP_C  1uF  Voltage rating: 6.3V  [CC0402N1R]
Cramp_C  200pF  Voltage rating: 50V  [CC0402N1R]
DONEC  SP1.5S  [SP1.5SQ]  (value not drawn)  (no BOM)
ISELC  SP1.5S  [SP1.5SQ]  (value not drawn)  (no BOM)
MON_TimingC  SP1.5S  [SP1.5SQ]  (value not drawn)  (no BOM)
R1_C  4.7k  [RC0603N1R]
R1C  1k  [RC0402N1R]
R2_C  4.7k  [RC0603N1R]
R2C  1k  [RC0402N1R]
R3C  1k  [RC0402N1R]
R4C  1K  [RC0402N1R]
R5C  1K  [RC0402N1R]
R6C  1K  [RC0402N1R]
R7C  1K  [RC0402N1R]
R8C  1K  [RC0402N1R]
R9C  1K  [RC0402N1R]
R10C  1K  [RC0402N1R]
R11C  1K  [RC0402N1R]
R12C  1K  [RC0402N1R]
R13C  1K  [RC0402N1R]
R14C  1K  [RC0402N1R]
R15C  1K  [RC0402N1R]
R16C  1K  [RC0402N1R]
R_BF1_C  1.3K  [RC0402N1R]
R_BF2_C  2K  [RC0402N1R]
R_Trig_C  100R  [RC0805N1R]
RampMONC  SP1.5S  [SP1.5SQ]  (value not drawn)  (no BOM)
RsstC  100R  [RC0402N1R]
UC  TargetX  [TQFP128_MZA]
VadjNC  SP1.5S  [SP1.5SQ]  (value not drawn)  (no BOM)
VadjPC  SP1.5S  [SP1.5SQ]  (value not drawn)  (no BOM)
VdisC  SP1.5S  [SP1.5SQ]  (value not drawn)  (no BOM)
VrampC  SP1.5S  [SP1.5SQ]  (value not drawn)  (no BOM)

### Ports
CLR (bidir), DO_[1..16] (out), PCLK_C (bidir), Ramp (bidir), RD_CS_S0 (bidir), RD_CS_S1 (bidir), RD_CS_S2 (bidir), RD_CS_S3 (bidir), RD_CS_S4 (bidir), RD_CS_S5 (bidir), RD_RS_S0 (bidir), RD_RS_S1 (bidir), RD_RS_S2 (bidir), RegCLR (bidir), RFin_1_C (in), RFin_2_C (in), RFin_3_C (in), RFin_4_C (in), RFin_5_C (in), RFin_6_C (in), RFin_7_C (in), RFin_8_C (in), RFin_9_C (in), RFin_10_C (in), RFin_11_C (in), RFin_12_C (in), RFin_13_C (in), RFin_14_C (in), RFin_15_C (in), RFin_16_C (in), SCLK (bidir), SHoutC, SIN (bidir), SmplSel_S1 (bidir), SmplSel_S2 (bidir), SmplSel_S3 (bidir), SmplSel_S4 (bidir), SmplSel_S5 (bidir), SmplSl_AnyC (in), SR_Clock (bidir), SR_Sel (bidir), TRG_C (out), TX_AC_SSTin_N (bidir), TX_AC_SSTin_P (bidir), TX_AC_WL_CLK_N (bidir), TX_AC_WL_CLK_P (bidir), Vped1 (bidir), WR_AddClr (bidir), WR_ENA (bidir)

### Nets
2.5V: Bf_C.5(V+) C1C.2 C2C.2 C3C.2 C4C.2 C5C.2 C6C.2 C7C.2 C8C.2 C9C.2 C10C.2 C11C.2 C12C.2 C13C.2 C14C.2 R2_C.1 R_BF1_C.2 R_Trig_C.2 UC.34(Vdd) UC.40(Vdd) UC.52(Vdd) UC.60(Vdd) UC.67(Vdd) UC.77(Vdd) UC.82(Vdd) UC.92(Vdd) UC.97(Vdd) UC.102(Vdd) UC.107(Vdd) UC.115(Vdd) UC.120(Vdd) UC.128(Vdd)
GND: Bf_C.2(V-) C1.2(Source) C1C.1 C2.2(Source) C2C.1 C3.2(Source) C3C.1 C4.2(Source) C4C.1 C5.2(Source) C5C.1 C6C.1 C7C.1 C8C.1 C9C.1 C10C.1 C11C.1 C12C.1 C13C.1 C14C.1 CDisC.1 CN_C.1 CP_C.1 Cramp_C.1 R1_C.1 R_BF2_C.1 UC.2(RFN_1) UC.4(RFN_2) UC.6(RFN_3) UC.8(RFN_4) UC.10(RFN_5) UC.12(RFN_6) UC.14(RFN_7) UC.16(RFN_8) UC.18(RFN_9) UC.20(RFN_10) UC.22(RFN_11) UC.24(RFN_12) UC.26(RFN_13) UC.28(RFN_14) UC.30(RFN_15) UC.32(RFN_16) UC.33(GND) UC.39(GND) UC.45(GND) UC.53(GND) UC.59(GND) UC.68(GND) UC.78(GND) UC.83(GND) UC.93(GND) UC.96(GND) UC.98(GND) UC.101(GND) UC.106(GND) UC.109(CMP_VSS) UC.114(GND) UC.117(GND) UC.121(GND) UC.123(GND) UC.127(GND)
DO_1: UC.91(DO_1)
DO_2: UC.90(DO_2)
DO_3: UC.89(DO_3)
DO_4: UC.88(DO_4)
DO_5: UC.87(DO_5)
DO_6: UC.86(DO_6)
DO_7: UC.85(DO_7)
DO_8: UC.84(DO_8)
DO_9: UC.76(DO_9)
DO_10: UC.75(DO_10)
DO_11: UC.74(DO_11)
DO_12: UC.73(DO_12)
DO_13: UC.72(DO_13)
DO_14: UC.71(DO_14)
DO_15: UC.70(DO_15)
DO_16: UC.69(DO_16)
ISEL_C: ISELC.1 UC.112(ISEL)
PCLK_C: UC.37(PCLK) ; port PCLK_C
RampMon_C: RampMONC.1 UC.111(RampMon)
RD_CS_S0: UC.46(RD_CS_S0) ; port RD_CS_S0
RD_CS_S1: UC.47(RD_CS_S1) ; port RD_CS_S1
RD_CS_S2: UC.48(RD_CS_S2) ; port RD_CS_S2
RD_CS_S3: UC.49(RD_CS_S3) ; port RD_CS_S3
RD_CS_S4: UC.50(RD_CS_S4) ; port RD_CS_S4
RD_CS_S5: UC.51(RD_CS_S5) ; port RD_CS_S5
RD_RS_S0: UC.105(RD_RS_S0) ; port RD_RS_S0
RD_RS_S1: UC.104(RD_RS_S1) ; port RD_RS_S1
RD_RS_S2: UC.103(RD_RS_S2) ; port RD_RS_S2
RegCLR: UC.99(RegCLR) ; port RegCLR
RFin_1_C: R1C.2 UC.1(RFin_1) ; port RFin_1_C
RFin_2_C: R2C.2 UC.3(RFin_2) ; port RFin_2_C
RFin_3_C: R3C.2 UC.5(RFin_3) ; port RFin_3_C
RFin_4_C: R4C.2 UC.7(RFin_4) ; port RFin_4_C
RFin_5_C: R5C.2 UC.9(RFin_5) ; port RFin_5_C
RFin_6_C: R6C.2 UC.11(RFin_6) ; port RFin_6_C
RFin_7_C: R7C.2 UC.13(RFin_7) ; port RFin_7_C
RFin_8_C: R8C.2 UC.15(RFin_8) ; port RFin_8_C
RFin_9_C: R9C.2 UC.17(RFin_9) ; port RFin_9_C
RFin_10_C: R10C.2 UC.19(RFin_10) ; port RFin_10_C
RFin_11_C: R11C.2 UC.21(RFin_11) ; port RFin_11_C
RFin_12_C: R12C.2 UC.23(RFin_12) ; port RFin_12_C
RFin_13_C: R13C.2 UC.25(RFin_13) ; port RFin_13_C
RFin_14_C: R14C.2 UC.27(RFin_14) ; port RFin_14_C
RFin_15_C: R15C.2 UC.29(RFin_15) ; port RFin_15_C
RFin_16_C: R16C.2 UC.31(RFin_16) ; port RFin_16_C
SCLK: UC.36(SCLK) ; port SCLK
SHoutC: UC.38(SHout) ; port SHoutC
SIN: UC.35(SIN) ; port SIN
SmplSel_S1: UC.65(SmplSel_S1) ; port SmplSel_S1
SmplSel_S2: UC.64(SmplSel_S2) ; port SmplSel_S2
SmplSel_S3: UC.63(SmplSel_S3) ; port SmplSel_S3
SmplSel_S4: UC.62(SmplSel_S4) ; port SmplSel_S4
SmplSel_S5: UC.61(SmplSel_S5) ; port SmplSel_S5
SmplSl_AnyC: UC.66(SmplSl_Any) ; port SmplSl_AnyC
SR_Clock: UC.80(SR_Clock) ; port SR_Clock
SR_Sel: UC.81(SR_SEL) ; port SR_Sel
TRG_C: C1.3(Drain) C2.3(Drain) C3.3(Drain) C4.3(Drain) C5.3(Drain) R_Trig_C.1 ; port TRG_C
TX_AC_SSTin_N: RsstC.1 UC.126(SSTin_n) ; port TX_AC_SSTin_N
TX_AC_SSTin_P: RsstC.2 UC.125(SSTin_P) ; port TX_AC_SSTin_P
TX_AC_WL_CLK_N: UC.57(WL_CLK_n) ; port TX_AC_WL_CLK_N
TX_AC_WL_CLK_P: UC.58(WL_CLK_p) ; port TX_AC_WL_CLK_P
VadjNC: CN_C.2 UC.122(VadjN) VadjNC.1
VadjPC: CP_C.2 UC.124(VadjP) VadjPC.1
Vdischarge_C: CDisC.2 UC.110(Vdischarge) VdisC.1
Vped1: Bf_C.1(OUT) Bf_C.4(-IN) R1C.1 R2C.1 R3C.1 R4C.1 R5C.1 R6C.1 R7C.1 R8C.1 R9C.1 R10C.1 R11C.1 R12C.1 R13C.1 R14C.1 R15C.1 R16C.1 ; port Vped1
VrampRef_C: Cramp_C.2 UC.113(VrampRef) VrampC.1
WR_AddClr: UC.54(WR_AddrClr) ; port WR_AddClr
WR_ENA: UC.55(WR1_Ena) UC.56(WR2_Ena) ; port WR_ENA
NetBf_C_3: Bf_C.3(+IN) R_BF1_C.1 R_BF2_C.2
NetC1_1: C1.1(Gate) UC.119(TRG_1)
NetC2_1: C2.1(Gate) UC.118(TRG_2)
NetC3_1: C3.1(Gate) UC.41(TRG_3)
NetC4_1: C4.1(Gate) UC.42(TRG_4)
NetC5_1: C5.1(Gate) UC.44(TRG_16)
NetDONEC_1: DONEC.1 UC.94(DONE)
NetMON_TimingC_1: MON_TimingC.1 UC.116(MON_Timing)
NetR1_C_2: R1_C.2 UC.79(SR_Clear)
NetR2_C_2: R2_C.2 UC.100(RD_ENA)

Not connected (* = marked no-connect by the designer): UC 43(TRG_5) 95(CLR) 108(Ramp)

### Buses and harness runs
bus DO_[1..16] = port DO_[1..16]

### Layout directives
differential pair; rule Differential Pairs Routing [Pref Gap = 0.254mm    Min Gap  = 0.254mm    Max Gap  = 0.254mmPref Width = 0.381mm    Min Width  = 0.381mm    Max Width  = 0.381mm]: TX_AC_WL_CLK_P
differential pair; rule Differential Pairs Routing [Pref Gap = 10mil    Min Gap  = 10mil    Max Gap  = 10milPref Width = 15mil    Min Width  = 15mil    Max Width  = 15mil]: TX_AC_SSTin_N, TX_AC_SSTin_P, TX_AC_WL_CLK_N

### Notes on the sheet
- 700mW
- 280mA
- (near VadjPC) WARNING!!
- Board:
- High Energy Physics Group, Instrumentation Development Lab
- Drawn By:
- Designer:
- Approved By:
- Revision:
- IDLAB design #:
- Variant:
- IDL_18_011
- Sheet Title:
- TargetX_C
- Modif. Date:
- Sheet       of

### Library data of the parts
Bf_C = LT1797CS5#TRMPBF: Buffer Op-Amp
C1-C5 = RUM001L02: as A1 on sheet TargetX_A
C1C C2C C3C C4C C5C C6C C7C C8C C9C C10C C11C C12C C13C C14C = CAPCC0402_100N_50VX7R: as C1A on sheet TargetX_A
CDisC CN_C CP_C = CAPCC0402_1.0U_50VX7R: as CDisA on sheet TargetX_A
Cramp_C = CAPCC0402_200P_50VNP0: as Cr_A on sheet TargetX_A
DONEC ISELC MON_TimingC RampMONC VadjNC VadjPC VdisC VrampC = SP1.5S: as DONEA on sheet TargetX_A
R1_C R2_C = RES0603-1-1.00K-1%100PPM: as R1_A on sheet TargetX_A
R1C R2C R3C R4C R5C R6C R7C R8C R9C R10C R11C R12C R13C R14C R15C R16C R_BF1_C R_BF2_C = RES0402-0-0R-1%100PPM: as R1A on sheet TargetX_A
R_Trig_C = RES0805: as R_Trig_A on sheet TargetX_A
RsstC = RES0402-100R-1%100PPM: as RwA on sheet TargetX_A
UC = DIGITZ_TargetX: as UA on sheet TargetX_A

## Sheet TargetX_D.SchDoc
size 401 x 291 mm; DocumentNumber: 4; SheetNumber: 4; SheetTotal: 4
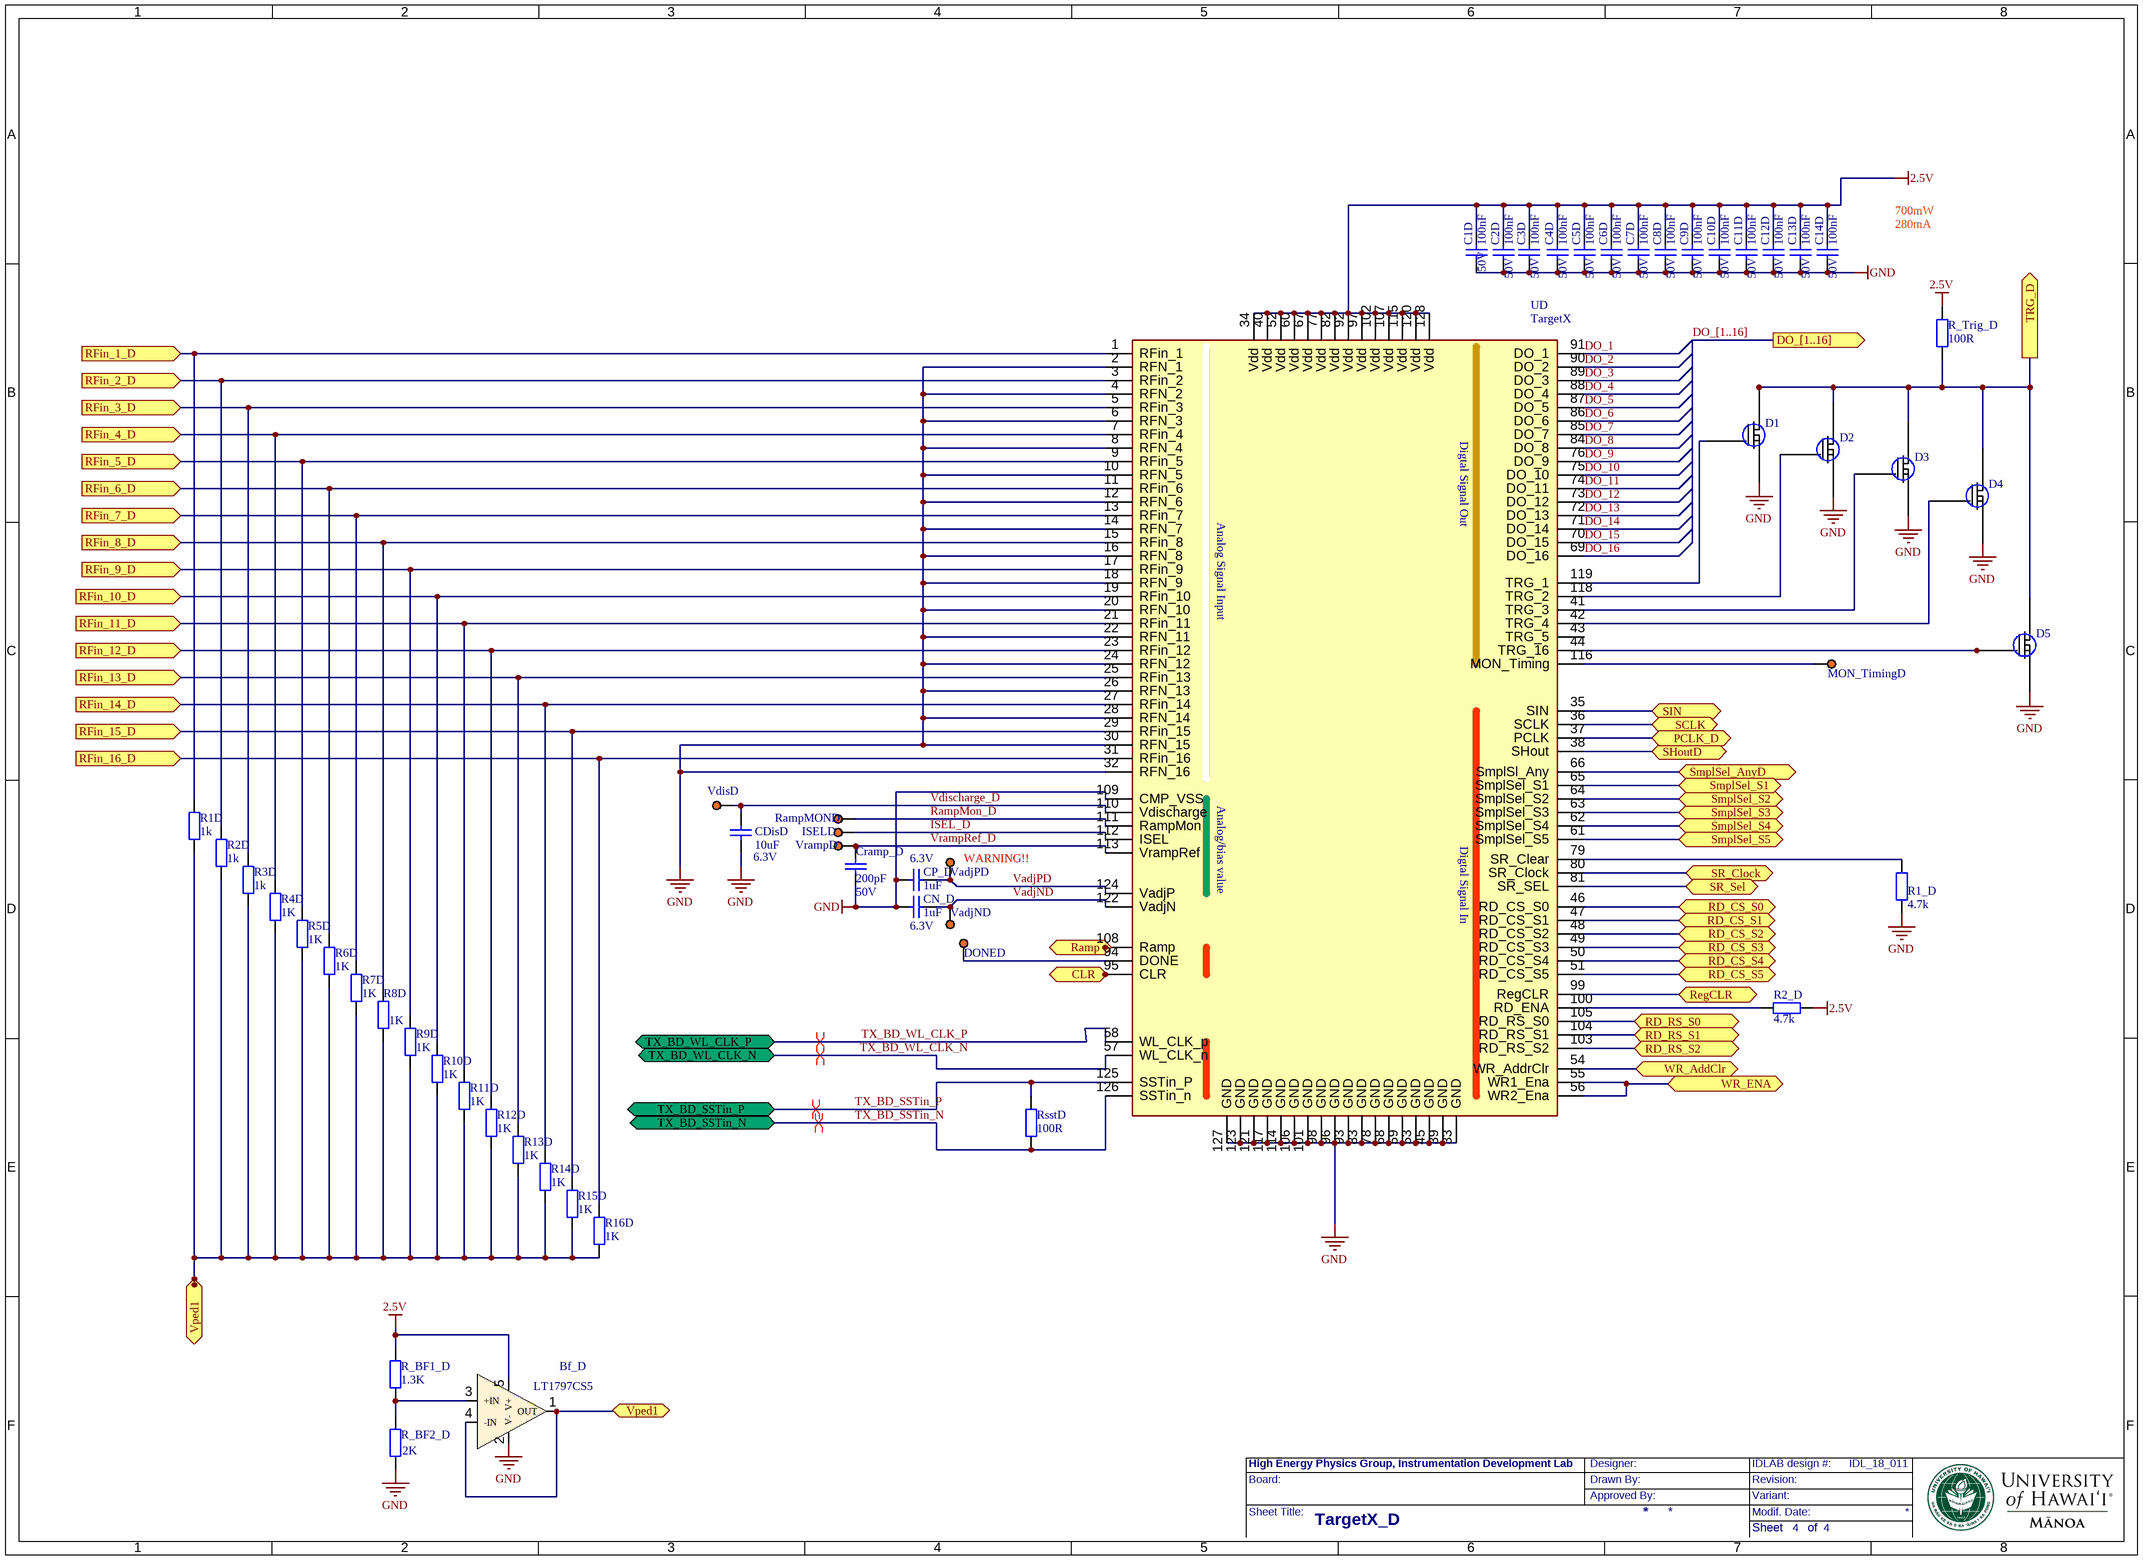
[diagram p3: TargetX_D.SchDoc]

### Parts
Bf_D  LT1797CS5  [TSOT23-5]
C1D  100nF  Voltage rating: 50V  [CC0402N1R]
C2D  100nF  Voltage rating: 50V  [CC0402N1R]
C3D  100nF  Voltage rating: 50V  [CC0402N1R]
C4D  100nF  Voltage rating: 50V  [CC0402N1R]
C5D  100nF  Voltage rating: 50V  [CC0402N1R]
C6D  100nF  Voltage rating: 50V  [CC0402N1R]
C7D  100nF  Voltage rating: 50V  [CC0402N1R]
C8D  100nF  Voltage rating: 50V  [CC0402N1R]
C9D  100nF  Voltage rating: 50V  [CC0402N1R]
C10D  100nF  Voltage rating: 50V  [CC0402N1R]
C11D  100nF  Voltage rating: 50V  [CC0402N1R]
C12D  100nF  Voltage rating: 50V  [CC0402N1R]
C13D  100nF  Voltage rating: 50V  [CC0402N1R]
C14D  100nF  Voltage rating: 50V  [CC0402N1R]
CDisD  10uF  Voltage rating: 6.3V  [CC0402N1R]
CN_D  1uF  Voltage rating: 6.3V  [CC0402N1R]
CP_D  1uF  Voltage rating: 6.3V  [CC0402N1R]
Cramp_D  200pF  Voltage rating: 50V  [CC0402N1R]
D1  MOSFET  [SOT-723]  (value not drawn)
D2  MOSFET  [SOT-723]  (value not drawn)
D3  MOSFET  [SOT-723]  (value not drawn)
D4  MOSFET  [SOT-723]  (value not drawn)
D5  MOSFET  [SOT-723]  (value not drawn)
DONED  (no value)  [SP1.5SQ]  (no BOM)
ISELD  (no value)  [SP1.5SQ]  (no BOM)
MON_TimingD  SP1.5S  [SP1.5SQ]  (value not drawn)  (no BOM)
R1_D  4.7k  [RC0603N1R]
R1D  1k  [RC0402N1R]
R2_D  4.7k  [RC0603N1R]
R2D  1k  [RC0402N1R]
R3D  1k  [RC0402N1R]
R4D  1K  [RC0402N1R]
R5D  1K  [RC0402N1R]
R6D  1K  [RC0402N1R]
R7D  1K  [RC0402N1R]
R8D  1K  [RC0402N1R]
R9D  1K  [RC0402N1R]
R10D  1K  [RC0402N1R]
R11D  1K  [RC0402N1R]
R12D  1K  [RC0402N1R]
R13D  1K  [RC0402N1R]
R14D  1K  [RC0402N1R]
R15D  1K  [RC0402N1R]
R16D  1K  [RC0402N1R]
R_BF1_D  1.3K  [RC0402N1R]
R_BF2_D  2K  [RC0402N1R]
R_Trig_D  100R  [RC0805N1R]
RampMOND  (no value)  [SP1.5SQ]  (no BOM)
RsstD  100R  [RC0402N1R]
UD  TargetX  [TQFP128_MZA]
VadjND  (no value)  [SP1.5SQ]  (no BOM)
VadjPD  (no value)  [SP1.5SQ]  (no BOM)
VdisD  SP1.5S  [SP1.5SQ]  (value not drawn)  (no BOM)
VrampD  SP1.5S  [SP1.5SQ]  (value not drawn)  (no BOM)

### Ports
CLR (bidir), DO_[1..16] (out), PCLK_D (bidir), Ramp (bidir), RD_CS_S0 (bidir), RD_CS_S1 (bidir), RD_CS_S2 (bidir), RD_CS_S3 (bidir), RD_CS_S4 (bidir), RD_CS_S5 (bidir), RD_RS_S0 (bidir), RD_RS_S1 (bidir), RD_RS_S2 (bidir), RegCLR (bidir), RFin_1_D (in), RFin_2_D (in), RFin_3_D (in), RFin_4_D (in), RFin_5_D (in), RFin_6_D (in), RFin_7_D (in), RFin_8_D (in), RFin_9_D (in), RFin_10_D (in), RFin_11_D (in), RFin_12_D (in), RFin_13_D (in), RFin_14_D (in), RFin_15_D (in), RFin_16_D (in), SCLK (bidir), SHoutD (bidir), SIN (bidir), SmplSel_AnyD (bidir), SmplSel_S1 (bidir), SmplSel_S2 (bidir), SmplSel_S3 (bidir), SmplSel_S4 (bidir), SmplSel_S5 (bidir), SR_Clock (bidir), SR_Sel (bidir), TRG_D (out), TX_BD_SSTin_N (bidir), TX_BD_SSTin_P (bidir), TX_BD_WL_CLK_N (bidir), TX_BD_WL_CLK_P (bidir), Vped1 (bidir), WR_AddClr (bidir), WR_ENA (bidir)

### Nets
2.5V: Bf_D.5(V+) C1D.2 C2D.2 C3D.2 C4D.2 C5D.2 C6D.2 C7D.2 C8D.2 C9D.2 C10D.2 C11D.2 C12D.2 C13D.2 C14D.2 R2_D.1 R_BF1_D.2 R_Trig_D.2 UD.34(Vdd) UD.40(Vdd) UD.52(Vdd) UD.60(Vdd) UD.67(Vdd) UD.77(Vdd) UD.82(Vdd) UD.92(Vdd) UD.97(Vdd) UD.102(Vdd) UD.107(Vdd) UD.115(Vdd) UD.120(Vdd) UD.128(Vdd)
GND: Bf_D.2(V-) C1D.1 C2D.1 C3D.1 C4D.1 C5D.1 C6D.1 C7D.1 C8D.1 C9D.1 C10D.1 C11D.1 C12D.1 C13D.1 C14D.1 CDisD.1 CN_D.1 CP_D.1 Cramp_D.1 D1.2(Source) D2.2(Source) D3.2(Source) D4.2(Source) D5.2(Source) R1_D.1 R_BF2_D.1 UD.2(RFN_1) UD.4(RFN_2) UD.6(RFN_3) UD.8(RFN_4) UD.10(RFN_5) UD.12(RFN_6) UD.14(RFN_7) UD.16(RFN_8) UD.18(RFN_9) UD.20(RFN_10) UD.22(RFN_11) UD.24(RFN_12) UD.26(RFN_13) UD.28(RFN_14) UD.30(RFN_15) UD.32(RFN_16) UD.33(GND) UD.39(GND) UD.45(GND) UD.53(GND) UD.59(GND) UD.68(GND) UD.78(GND) UD.83(GND) UD.93(GND) UD.96(GND) UD.98(GND) UD.101(GND) UD.106(GND) UD.109(CMP_VSS) UD.114(GND) UD.117(GND) UD.121(GND) UD.123(GND) UD.127(GND)
DO_1: UD.91(DO_1)
DO_2: UD.90(DO_2)
DO_3: UD.89(DO_3)
DO_4: UD.88(DO_4)
DO_5: UD.87(DO_5)
DO_6: UD.86(DO_6)
DO_7: UD.85(DO_7)
DO_8: UD.84(DO_8)
DO_9: UD.76(DO_9)
DO_10: UD.75(DO_10)
DO_11: UD.74(DO_11)
DO_12: UD.73(DO_12)
DO_13: UD.72(DO_13)
DO_14: UD.71(DO_14)
DO_15: UD.70(DO_15)
DO_16: UD.69(DO_16)
ISEL_D: ISELD.1 UD.112(ISEL)
PCLK_D: UD.37(PCLK) ; port PCLK_D
RampMon_D: RampMOND.1 UD.111(RampMon)
RD_CS_S0: UD.46(RD_CS_S0) ; port RD_CS_S0
RD_CS_S1: UD.47(RD_CS_S1) ; port RD_CS_S1
RD_CS_S2: UD.48(RD_CS_S2) ; port RD_CS_S2
RD_CS_S3: UD.49(RD_CS_S3) ; port RD_CS_S3
RD_CS_S4: UD.50(RD_CS_S4) ; port RD_CS_S4
RD_CS_S5: UD.51(RD_CS_S5) ; port RD_CS_S5
RD_RS_S0: UD.105(RD_RS_S0) ; port RD_RS_S0
RD_RS_S1: UD.104(RD_RS_S1) ; port RD_RS_S1
RD_RS_S2: UD.103(RD_RS_S2) ; port RD_RS_S2
RegCLR: UD.99(RegCLR) ; port RegCLR
RFin_1_D: R1D.2 UD.1(RFin_1) ; port RFin_1_D
RFin_2_D: R2D.2 UD.3(RFin_2) ; port RFin_2_D
RFin_3_D: R3D.2 UD.5(RFin_3) ; port RFin_3_D
RFin_4_D: R4D.2 UD.7(RFin_4) ; port RFin_4_D
RFin_5_D: R5D.2 UD.9(RFin_5) ; port RFin_5_D
RFin_6_D: R6D.2 UD.11(RFin_6) ; port RFin_6_D
RFin_7_D: R7D.2 UD.13(RFin_7) ; port RFin_7_D
RFin_8_D: R8D.2 UD.15(RFin_8) ; port RFin_8_D
RFin_9_D: R9D.2 UD.17(RFin_9) ; port RFin_9_D
RFin_10_D: R10D.2 UD.19(RFin_10) ; port RFin_10_D
RFin_11_D: R11D.2 UD.21(RFin_11) ; port RFin_11_D
RFin_12_D: R12D.2 UD.23(RFin_12) ; port RFin_12_D
RFin_13_D: R13D.2 UD.25(RFin_13) ; port RFin_13_D
RFin_14_D: R14D.2 UD.27(RFin_14) ; port RFin_14_D
RFin_15_D: R15D.2 UD.29(RFin_15) ; port RFin_15_D
RFin_16_D: R16D.2 UD.31(RFin_16) ; port RFin_16_D
SCLK: UD.36(SCLK) ; port SCLK
SHoutD: UD.38(SHout) ; port SHoutD
SIN: UD.35(SIN) ; port SIN
SmplSel_AnyD: UD.66(SmplSl_Any) ; port SmplSel_AnyD
SmplSel_S1: UD.65(SmplSel_S1) ; port SmplSel_S1
SmplSel_S2: UD.64(SmplSel_S2) ; port SmplSel_S2
SmplSel_S3: UD.63(SmplSel_S3) ; port SmplSel_S3
SmplSel_S4: UD.62(SmplSel_S4) ; port SmplSel_S4
SmplSel_S5: UD.61(SmplSel_S5) ; port SmplSel_S5
SR_Clock: UD.80(SR_Clock) ; port SR_Clock
SR_Sel: UD.81(SR_SEL) ; port SR_Sel
TRG_D: D1.3(Drain) D2.3(Drain) D3.3(Drain) D4.3(Drain) D5.3(Drain) R_Trig_D.1 ; port TRG_D
TX_BD_SSTin_N: RsstD.1 UD.126(SSTin_n) ; port TX_BD_SSTin_N
TX_BD_SSTin_P: RsstD.2 UD.125(SSTin_P) ; port TX_BD_SSTin_P
TX_BD_WL_CLK_N: UD.57(WL_CLK_n) ; port TX_BD_WL_CLK_N
TX_BD_WL_CLK_P: UD.58(WL_CLK_p) ; port TX_BD_WL_CLK_P
VadjND: CN_D.2 UD.122(VadjN) VadjND.1
VadjPD: CP_D.2 UD.124(VadjP) VadjPD.1
Vdischarge_D: CDisD.2 UD.110(Vdischarge) VdisD.1
Vped1: Bf_D.1(OUT) Bf_D.4(-IN) R1D.1 R2D.1 R3D.1 R4D.1 R5D.1 R6D.1 R7D.1 R8D.1 R9D.1 R10D.1 R11D.1 R12D.1 R13D.1 R14D.1 R15D.1 R16D.1 ; port Vped1
VrampRef_D: Cramp_D.2 UD.113(VrampRef) VrampD.1
WR_AddClr: UD.54(WR_AddrClr) ; port WR_AddClr
WR_ENA: UD.55(WR1_Ena) UD.56(WR2_Ena) ; port WR_ENA
NetBf_D_3: Bf_D.3(+IN) R_BF1_D.1 R_BF2_D.2
NetD1_1: D1.1(Gate) UD.119(TRG_1)
NetD2_1: D2.1(Gate) UD.118(TRG_2)
NetD3_1: D3.1(Gate) UD.41(TRG_3)
NetD4_1: D4.1(Gate) UD.42(TRG_4)
NetD5_1: D5.1(Gate) UD.44(TRG_16)
NetDONED_1: DONED.1 UD.94(DONE)
NetMON_TimingD_1: MON_TimingD.1 UD.116(MON_Timing)
NetR1_D_2: R1_D.2 UD.79(SR_Clear)
NetR2_D_2: R2_D.2 UD.100(RD_ENA)

Not connected (* = marked no-connect by the designer): UD 43(TRG_5) 95(CLR) 108(Ramp)

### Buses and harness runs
bus DO_[1..16] = port DO_[1..16]

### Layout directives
differential pair: TX_BD_SSTin_N, TX_BD_SSTin_P, TX_BD_WL_CLK_N, TX_BD_WL_CLK_P

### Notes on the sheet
- 700mW
- 280mA
- (near VadjPD) WARNING!!
- Board:
- High Energy Physics Group, Instrumentation Development Lab
- Sheet Title:
- Drawn By:
- Designer:
- Approved By:
- Modif. Date:
- Revision:
- IDLAB design #:
- Variant:
- IDL_18_011
- TargetX_D
- Sheet       of

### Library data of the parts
Bf_D = LT1797CS5#TRMPBF: Buffer Op-Amp
C1D C2D C3D C4D C5D C6D C7D C8D C9D C10D C11D C12D C13D C14D = CAPCC0402_100N_50VX7R: as C1A on sheet TargetX_A
CDisD CN_D CP_D = CAPCC0402_1.0U_50VX7R: as CDisA on sheet TargetX_A
Cramp_D = CAPCC0402_200P_50VNP0: as Cr_A on sheet TargetX_A
D1-D5 = RUM001L02: as A1 on sheet TargetX_A
DONED ISELD MON_TimingD RampMOND VadjND VadjPD VdisD VrampD = SP1.5S: as DONEA on sheet TargetX_A
R1_D R2_D = RES0603-1-1.00K-1%100PPM: as R1_A on sheet TargetX_A
R1D R2D R3D R4D R5D R6D R7D R8D R9D R10D R11D R12D R13D R14D R15D R16D R_BF1_D R_BF2_D = RES0402-0-0R-1%100PPM: as R1A on sheet TargetX_A
R_Trig_D = RES0805: as R_Trig_A on sheet TargetX_A
RsstD = RES0402-100R-1%100PPM: as RwA on sheet TargetX_A
UD = DIGITZ_TargetX: as UA on sheet TargetX_A

## Sheet Daughtercard_Input_Output.SchDoc
size 401 x 291 mm
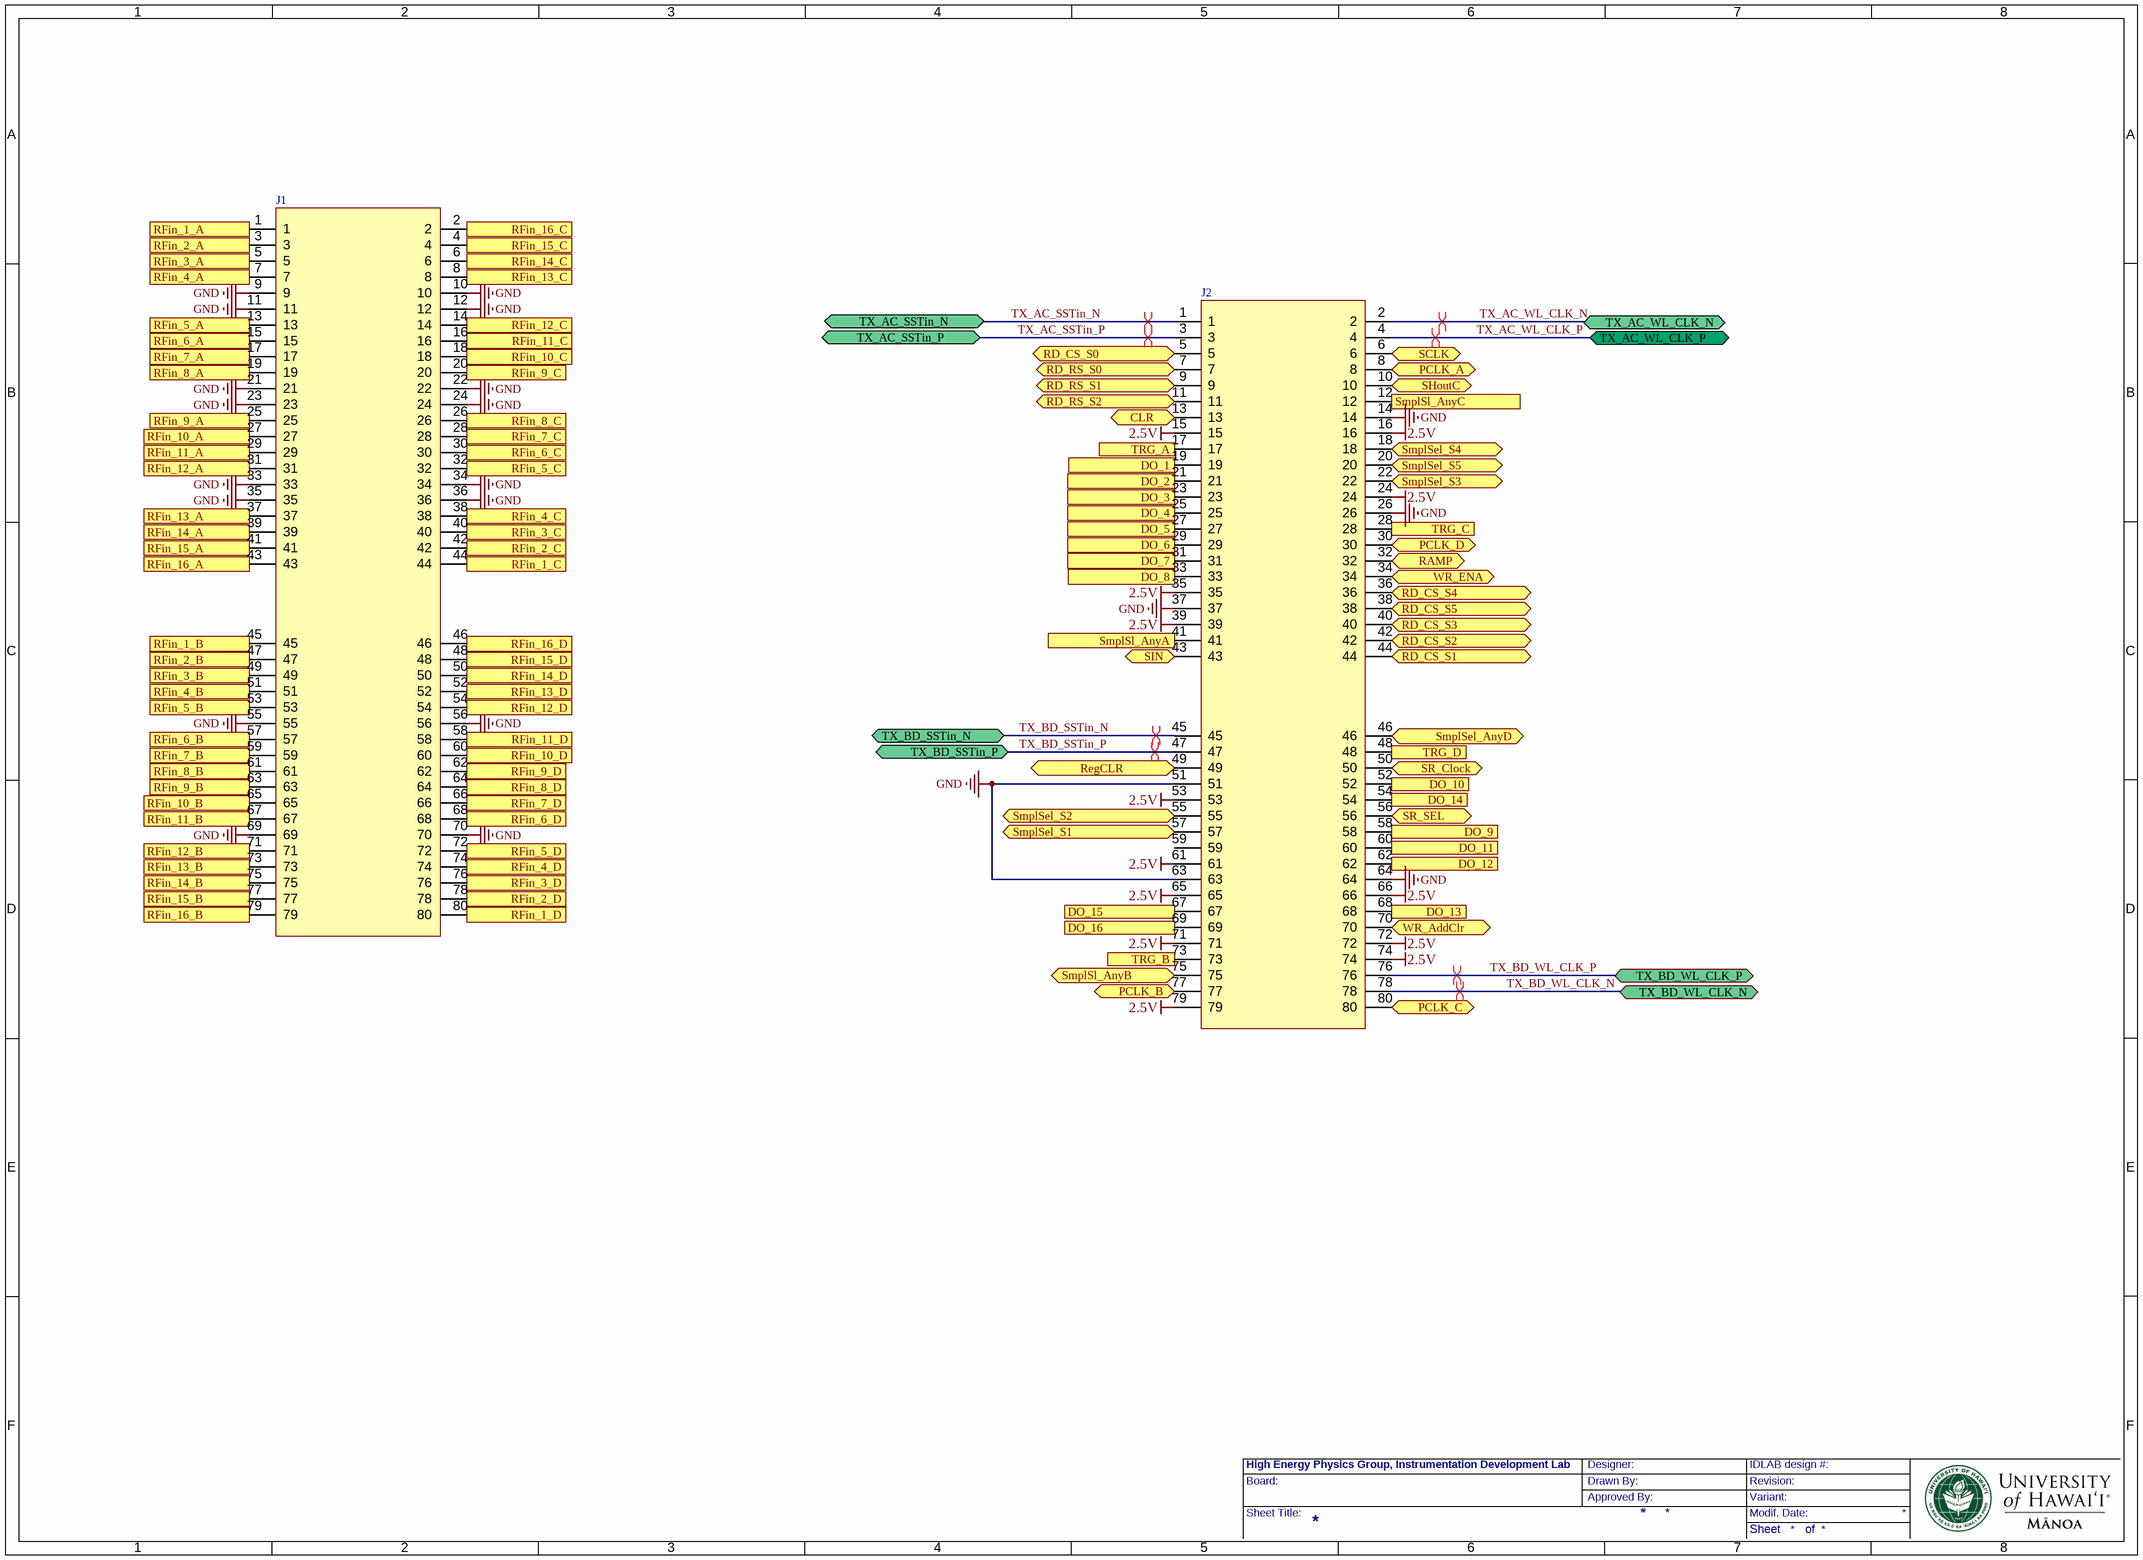
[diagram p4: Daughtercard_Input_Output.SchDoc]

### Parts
J1  SPD08 Card Edge Connector Mating Card Layout  [Card Edge Male]  (value not drawn)
J2  SPD08 Card Edge Connector Mating Card Layout  [Card Edge Male]  (value not drawn)

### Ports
CLR (bidir), DO_1 (in), DO_2 (in), DO_3 (in), DO_4 (in), DO_5 (in), DO_6 (in), DO_7 (in), DO_8 (in), DO_9 (in), DO_10 (in), DO_11 (in), DO_12 (in), DO_13 (in), DO_14 (in), DO_15 (in), DO_16 (in), PCLK_A (bidir), PCLK_B (bidir), PCLK_C (bidir), PCLK_D (bidir), RAMP (bidir), RD_CS_S0 (bidir), RD_CS_S1 (bidir), RD_CS_S2 (bidir), RD_CS_S3 (bidir), RD_CS_S4 (bidir), RD_CS_S5 (bidir), RD_RS_S0 (bidir), RD_RS_S1 (bidir), RD_RS_S2 (bidir), RegCLR (bidir), RFin_1_A (out), RFin_1_B (out), RFin_1_C (out), RFin_1_D (out), RFin_2_A (out), RFin_2_B (out), RFin_2_C (out), RFin_2_D (out), RFin_3_A (out), RFin_3_B (out), RFin_3_C (out), RFin_3_D (out), RFin_4_A (out), RFin_4_B (out), RFin_4_C (out), RFin_4_D (out), RFin_5_A (out), RFin_5_B (out), RFin_5_C (out), RFin_5_D (out), RFin_6_A (out), RFin_6_B (out), RFin_6_C (out), RFin_6_D (out), RFin_7_A (out), RFin_7_B (out), RFin_7_C (out), RFin_7_D (out), RFin_8_A (out), RFin_8_B (out), RFin_8_C (out), RFin_8_D (out), RFin_9_A (out), RFin_9_B (out), RFin_9_C (out), RFin_9_D (out), RFin_10_A (out), RFin_10_B (out), RFin_10_C (out), RFin_10_D (out), RFin_11_A (out), RFin_11_B (out), RFin_11_C (out), RFin_11_D (out), RFin_12_A (out), RFin_12_B (out), RFin_12_C (out), RFin_12_D (out), RFin_13_A (out), RFin_13_B (out), RFin_13_C (out), RFin_13_D (out), RFin_14_A (out), RFin_14_B (out), RFin_14_C (out), RFin_14_D (out), RFin_15_A (out), RFin_15_B (out), RFin_15_C (out), RFin_15_D (out), RFin_16_A (out), RFin_16_B (out), RFin_16_C (out), RFin_16_D (out), SCLK (bidir), SHoutC (bidir), SIN (bidir), SmplSel_AnyD (bidir), SmplSel_S1 (bidir), SmplSel_S2 (bidir), SmplSel_S3 (bidir), SmplSel_S4 (bidir), SmplSel_S5 (bidir), SmplSl_AnyA (out), SmplSl_AnyB (bidir), SmplSl_AnyC (out), SR_Clock (bidir), SR_SEL (bidir), TRG_A (out), TRG_B (out), TRG_C (in), TRG_D (out), TX_AC_SSTin_N (bidir), TX_AC_SSTin_P (bidir), TX_AC_WL_CLK_N (bidir), TX_AC_WL_CLK_P (bidir), TX_BD_SSTin_N (bidir), TX_BD_SSTin_P (bidir), TX_BD_WL_CLK_N (bidir), TX_BD_WL_CLK_P (bidir), WR_AddClr (bidir), WR_ENA (bidir)

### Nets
2.5V: J2.15 J2.16 J2.24 J2.35 J2.39 J2.53 J2.61 J2.65 J2.66 J2.71 J2.72 J2.74 J2.79
GND: J1.9 J1.10 J1.11 J1.12 J1.21 J1.22 J1.23 J1.24 J1.33 J1.34 J1.35 J1.36 J1.55 J1.56 J1.69 J1.70 J2.14 J2.26 J2.37 J2.51 J2.63 J2.64
CLR: J2.13 ; port CLR
DO_1: J2.19 ; port DO_1
DO_2: J2.21 ; port DO_2
DO_3: J2.23 ; port DO_3
DO_4: J2.25 ; port DO_4
DO_5: J2.27 ; port DO_5
DO_6: J2.29 ; port DO_6
DO_7: J2.31 ; port DO_7
DO_8: J2.33 ; port DO_8
DO_9: J2.58 ; port DO_9
DO_10: J2.52 ; port DO_10
DO_11: J2.60 ; port DO_11
DO_12: J2.62 ; port DO_12
DO_13: J2.68 ; port DO_13
DO_14: J2.54 ; port DO_14
DO_15: J2.67 ; port DO_15
DO_16: J2.69 ; port DO_16
PCLK_A: J2.8 ; port PCLK_A
PCLK_B: J2.77 ; port PCLK_B
PCLK_C: J2.80 ; port PCLK_C
PCLK_D: J2.30 ; port PCLK_D
Ramp: J2.32 ; port RAMP
RD_CS_S0: J2.5 ; port RD_CS_S0
RD_CS_S1: J2.44 ; port RD_CS_S1
RD_CS_S2: J2.42 ; port RD_CS_S2
RD_CS_S3: J2.40 ; port RD_CS_S3
RD_CS_S4: J2.36 ; port RD_CS_S4
RD_CS_S5: J2.38 ; port RD_CS_S5
RD_RS_S0: J2.7 ; port RD_RS_S0
RD_RS_S1: J2.9 ; port RD_RS_S1
RD_RS_S2: J2.11 ; port RD_RS_S2
RegCLR: J2.49 ; port RegCLR
RFin_1_A: J1.1 ; port RFin_1_A
RFin_1_B: J1.45 ; port RFin_1_B
RFin_1_C: J1.44 ; port RFin_1_C
RFin_1_D: J1.80 ; port RFin_1_D
RFin_2_A: J1.3 ; port RFin_2_A
RFin_2_B: J1.47 ; port RFin_2_B
RFin_2_C: J1.42 ; port RFin_2_C
RFin_2_D: J1.78 ; port RFin_2_D
RFin_3_A: J1.5 ; port RFin_3_A
RFin_3_B: J1.49 ; port RFin_3_B
RFin_3_C: J1.40 ; port RFin_3_C
RFin_3_D: J1.76 ; port RFin_3_D
RFin_4_A: J1.7 ; port RFin_4_A
RFin_4_B: J1.51 ; port RFin_4_B
RFin_4_C: J1.38 ; port RFin_4_C
RFin_4_D: J1.74 ; port RFin_4_D
RFin_5_A: J1.13 ; port RFin_5_A
RFin_5_B: J1.53 ; port RFin_5_B
RFin_5_C: J1.32 ; port RFin_5_C
RFin_5_D: J1.72 ; port RFin_5_D
RFin_6_A: J1.15 ; port RFin_6_A
RFin_6_B: J1.57 ; port RFin_6_B
RFin_6_C: J1.30 ; port RFin_6_C
RFin_6_D: J1.68 ; port RFin_6_D
RFin_7_A: J1.17 ; port RFin_7_A
RFin_7_B: J1.59 ; port RFin_7_B
RFin_7_C: J1.28 ; port RFin_7_C
RFin_7_D: J1.66 ; port RFin_7_D
RFin_8_A: J1.19 ; port RFin_8_A
RFin_8_B: J1.61 ; port RFin_8_B
RFin_8_C: J1.26 ; port RFin_8_C
RFin_8_D: J1.64 ; port RFin_8_D
RFin_9_A: J1.25 ; port RFin_9_A
RFin_9_B: J1.63 ; port RFin_9_B
RFin_9_C: J1.20 ; port RFin_9_C
RFin_9_D: J1.62 ; port RFin_9_D
RFin_10_A: J1.27 ; port RFin_10_A
RFin_10_B: J1.65 ; port RFin_10_B
RFin_10_C: J1.18 ; port RFin_10_C
RFin_10_D: J1.60 ; port RFin_10_D
RFin_11_A: J1.29 ; port RFin_11_A
RFin_11_B: J1.67 ; port RFin_11_B
RFin_11_C: J1.16 ; port RFin_11_C
RFin_11_D: J1.58 ; port RFin_11_D
RFin_12_A: J1.31 ; port RFin_12_A
RFin_12_B: J1.71 ; port RFin_12_B
RFin_12_C: J1.14 ; port RFin_12_C
RFin_12_D: J1.54 ; port RFin_12_D
RFin_13_A: J1.37 ; port RFin_13_A
RFin_13_B: J1.73 ; port RFin_13_B
RFin_13_C: J1.8 ; port RFin_13_C
RFin_13_D: J1.52 ; port RFin_13_D
RFin_14_A: J1.39 ; port RFin_14_A
RFin_14_B: J1.75 ; port RFin_14_B
RFin_14_C: J1.6 ; port RFin_14_C
RFin_14_D: J1.50 ; port RFin_14_D
RFin_15_A: J1.41 ; port RFin_15_A
RFin_15_B: J1.77 ; port RFin_15_B
RFin_15_C: J1.4 ; port RFin_15_C
RFin_15_D: J1.48 ; port RFin_15_D
RFin_16_A: J1.43 ; port RFin_16_A
RFin_16_B: J1.79 ; port RFin_16_B
RFin_16_C: J1.2 ; port RFin_16_C
RFin_16_D: J1.46 ; port RFin_16_D
SCLK: J2.6 ; port SCLK
SHoutC: J2.10 ; port SHoutC
SIN: J2.43 ; port SIN
SmplSel_AnyD: J2.46 ; port SmplSel_AnyD
SmplSel_S1: J2.57 ; port SmplSel_S1
SmplSel_S2: J2.55 ; port SmplSel_S2
SmplSel_S3: J2.22 ; port SmplSel_S3
SmplSel_S4: J2.18 ; port SmplSel_S4
SmplSel_S5: J2.20 ; port SmplSel_S5
SmplSl_AnyA: J2.41 ; port SmplSl_AnyA
SmplSl_AnyB: J2.75 ; port SmplSl_AnyB
SmplSl_AnyC: J2.12 ; port SmplSl_AnyC
SR_Clock: J2.50 ; port SR_Clock
SR_Sel: J2.56 ; port SR_SEL
TRG_A: J2.17 ; port TRG_A
TRG_B: J2.73 ; port TRG_B
TRG_C: J2.28 ; port TRG_C
TRG_D: J2.48 ; port TRG_D
TX_AC_SSTin_N: J2.1 ; port TX_AC_SSTin_N
TX_AC_SSTin_P: J2.3 ; port TX_AC_SSTin_P
TX_AC_WL_CLK_N: J2.2 ; port TX_AC_WL_CLK_N
TX_AC_WL_CLK_P: J2.4 ; port TX_AC_WL_CLK_P
TX_BD_SSTin_N: J2.45 ; port TX_BD_SSTin_N
TX_BD_SSTin_P: J2.47 ; port TX_BD_SSTin_P
TX_BD_WL_CLK_N: J2.78 ; port TX_BD_WL_CLK_N
TX_BD_WL_CLK_P: J2.76 ; port TX_BD_WL_CLK_P
WR_AddClr: J2.70 ; port WR_AddClr
WR_ENA: J2.34 ; port WR_ENA

Not connected (* = marked no-connect by the designer): J2 59

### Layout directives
differential pair: TX_AC_SSTin_N, TX_AC_SSTin_P, TX_AC_WL_CLK_N, TX_AC_WL_CLK_P, TX_BD_SSTin_N, TX_BD_SSTin_P, TX_BD_WL_CLK_N, TX_BD_WL_CLK_P

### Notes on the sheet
- Board:
- High Energy Physics Group, Instrumentation Development Lab
- Drawn By:
- Designer:
- Approved By:
- Revision:
- IDLAB design #:
- Variant:
- Sheet Title:
- Modif. Date:
- Sheet       of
